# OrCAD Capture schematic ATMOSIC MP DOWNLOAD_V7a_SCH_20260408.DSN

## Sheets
1 1. TITLE: title: Atmosic MP Download Board - TITLE; rev: 7a
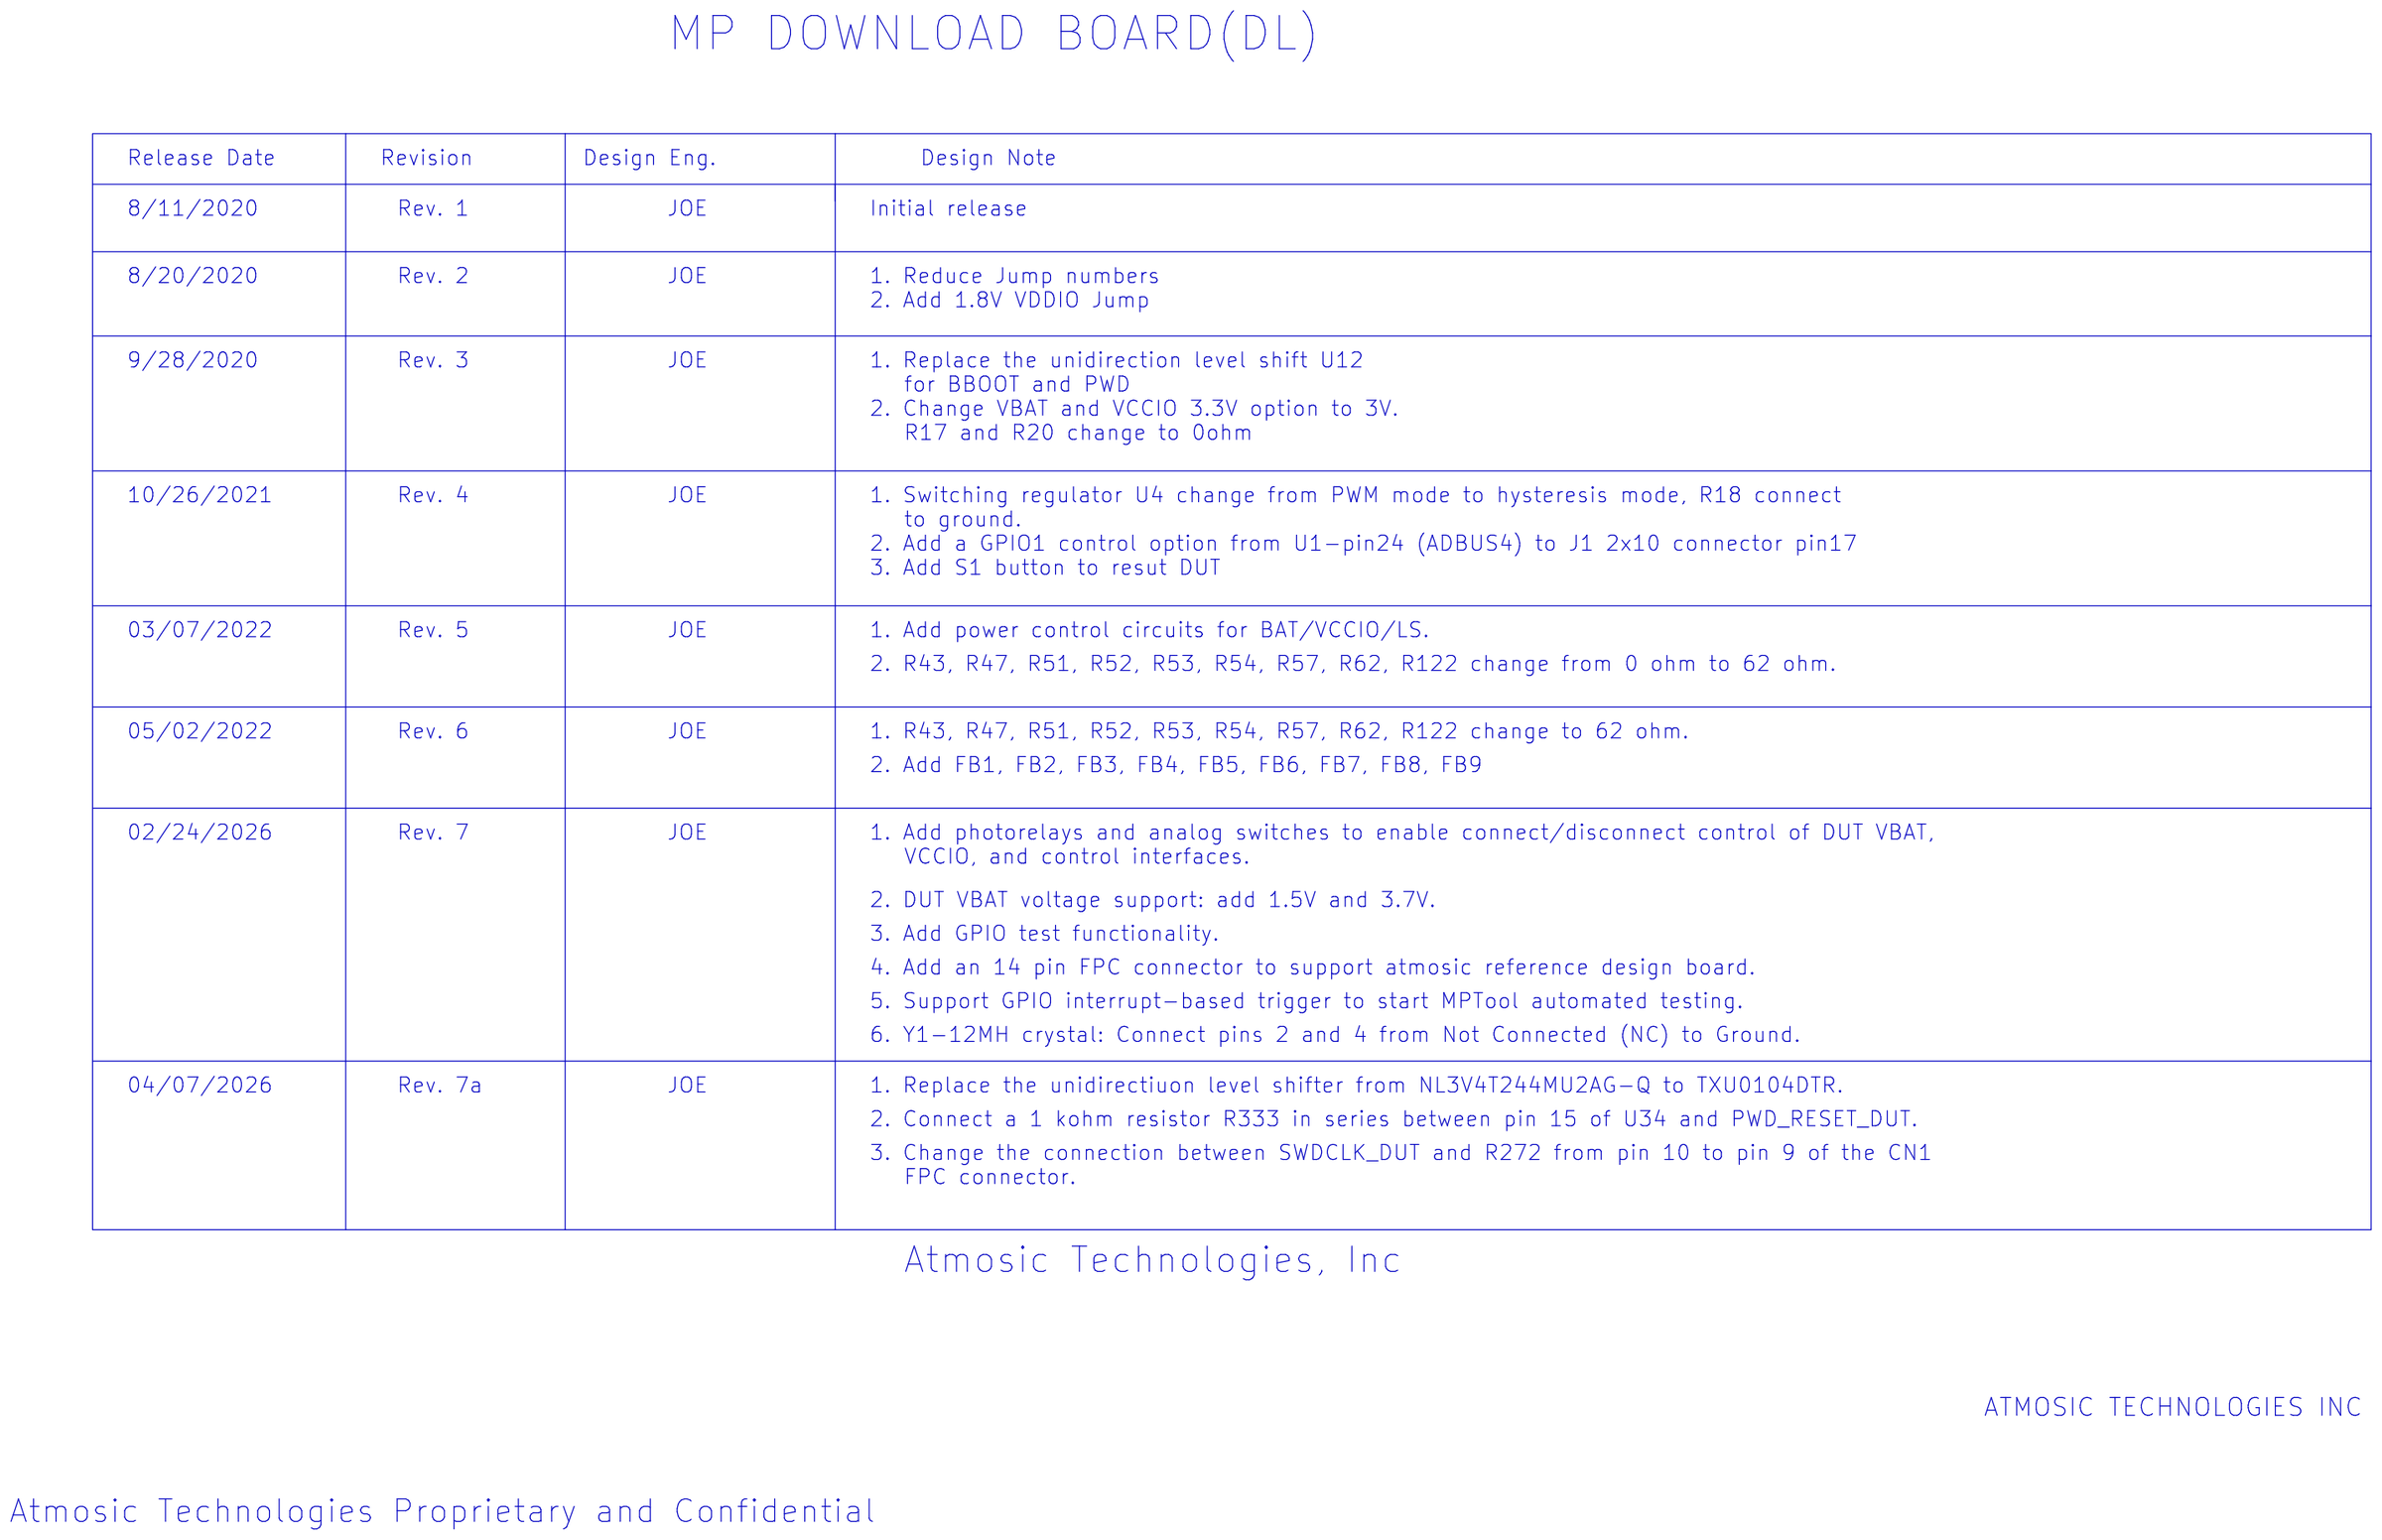
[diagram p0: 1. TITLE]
2 2. BLOCK_DIAGRAM: title: Atmosic MP Download Board - 2. BLOCK_DIAGRAM
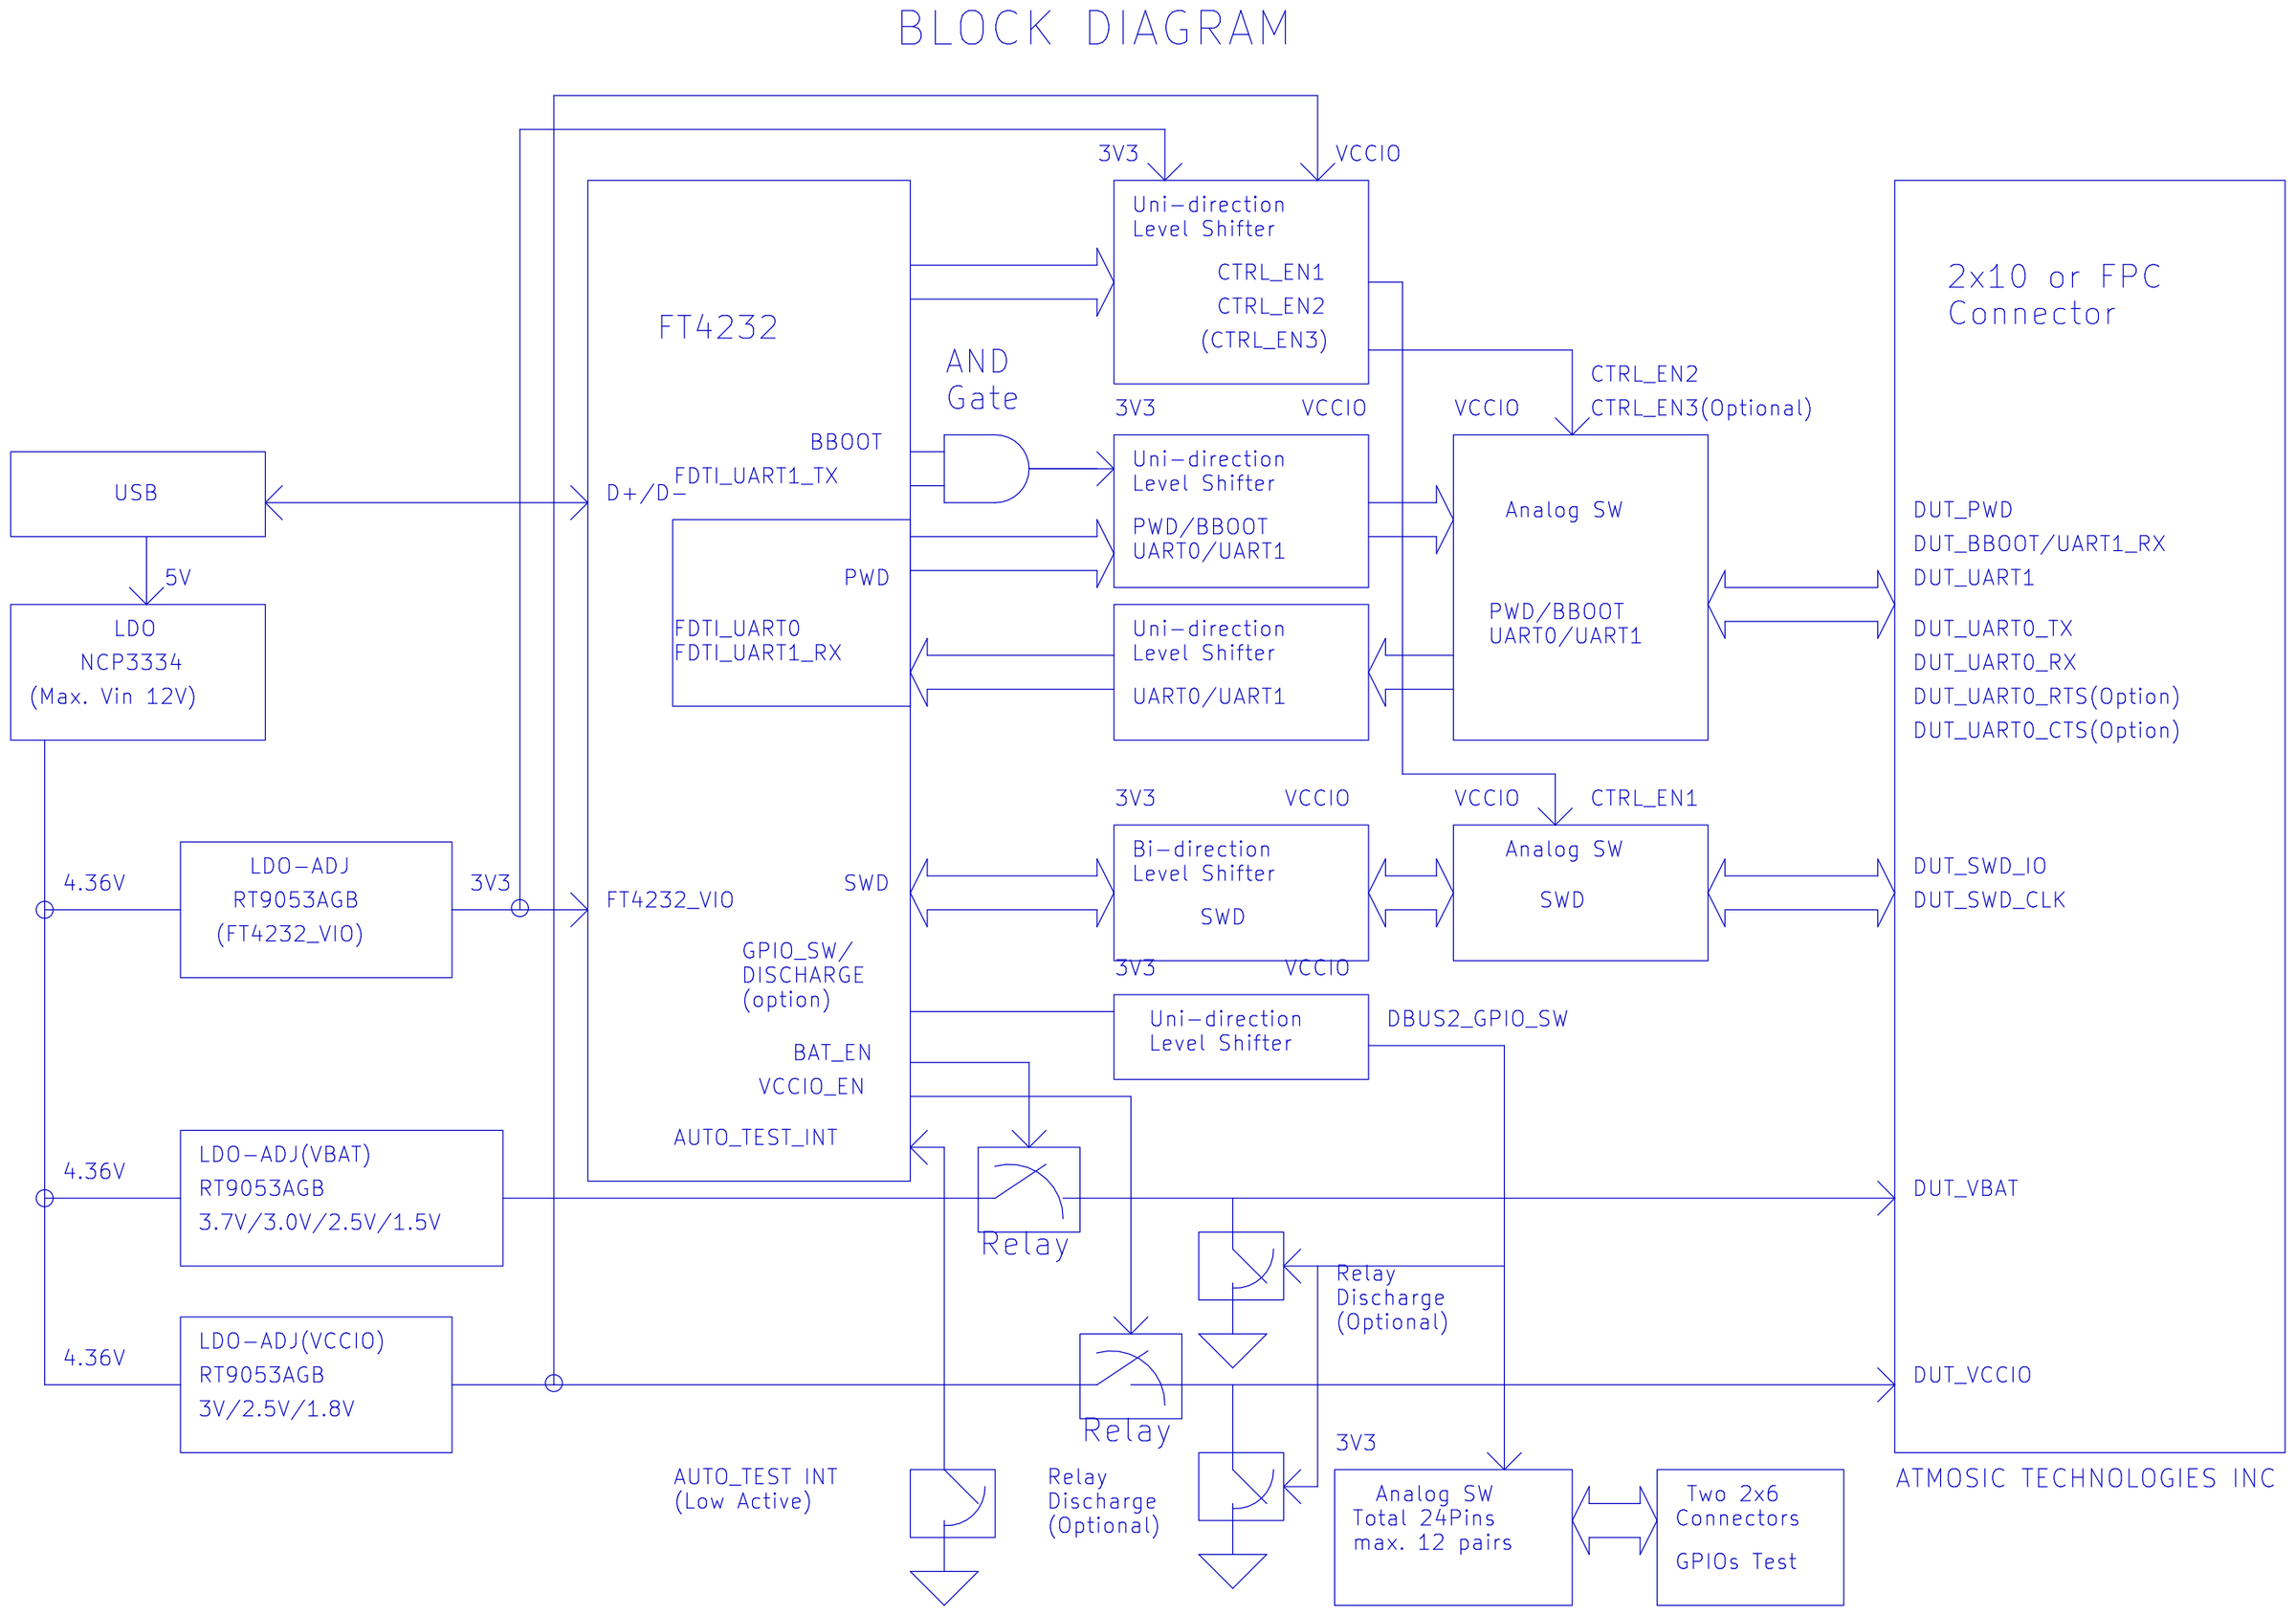
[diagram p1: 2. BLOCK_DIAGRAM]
3 3. POWER: size B; title: Atmosic MP Download Board - POWER
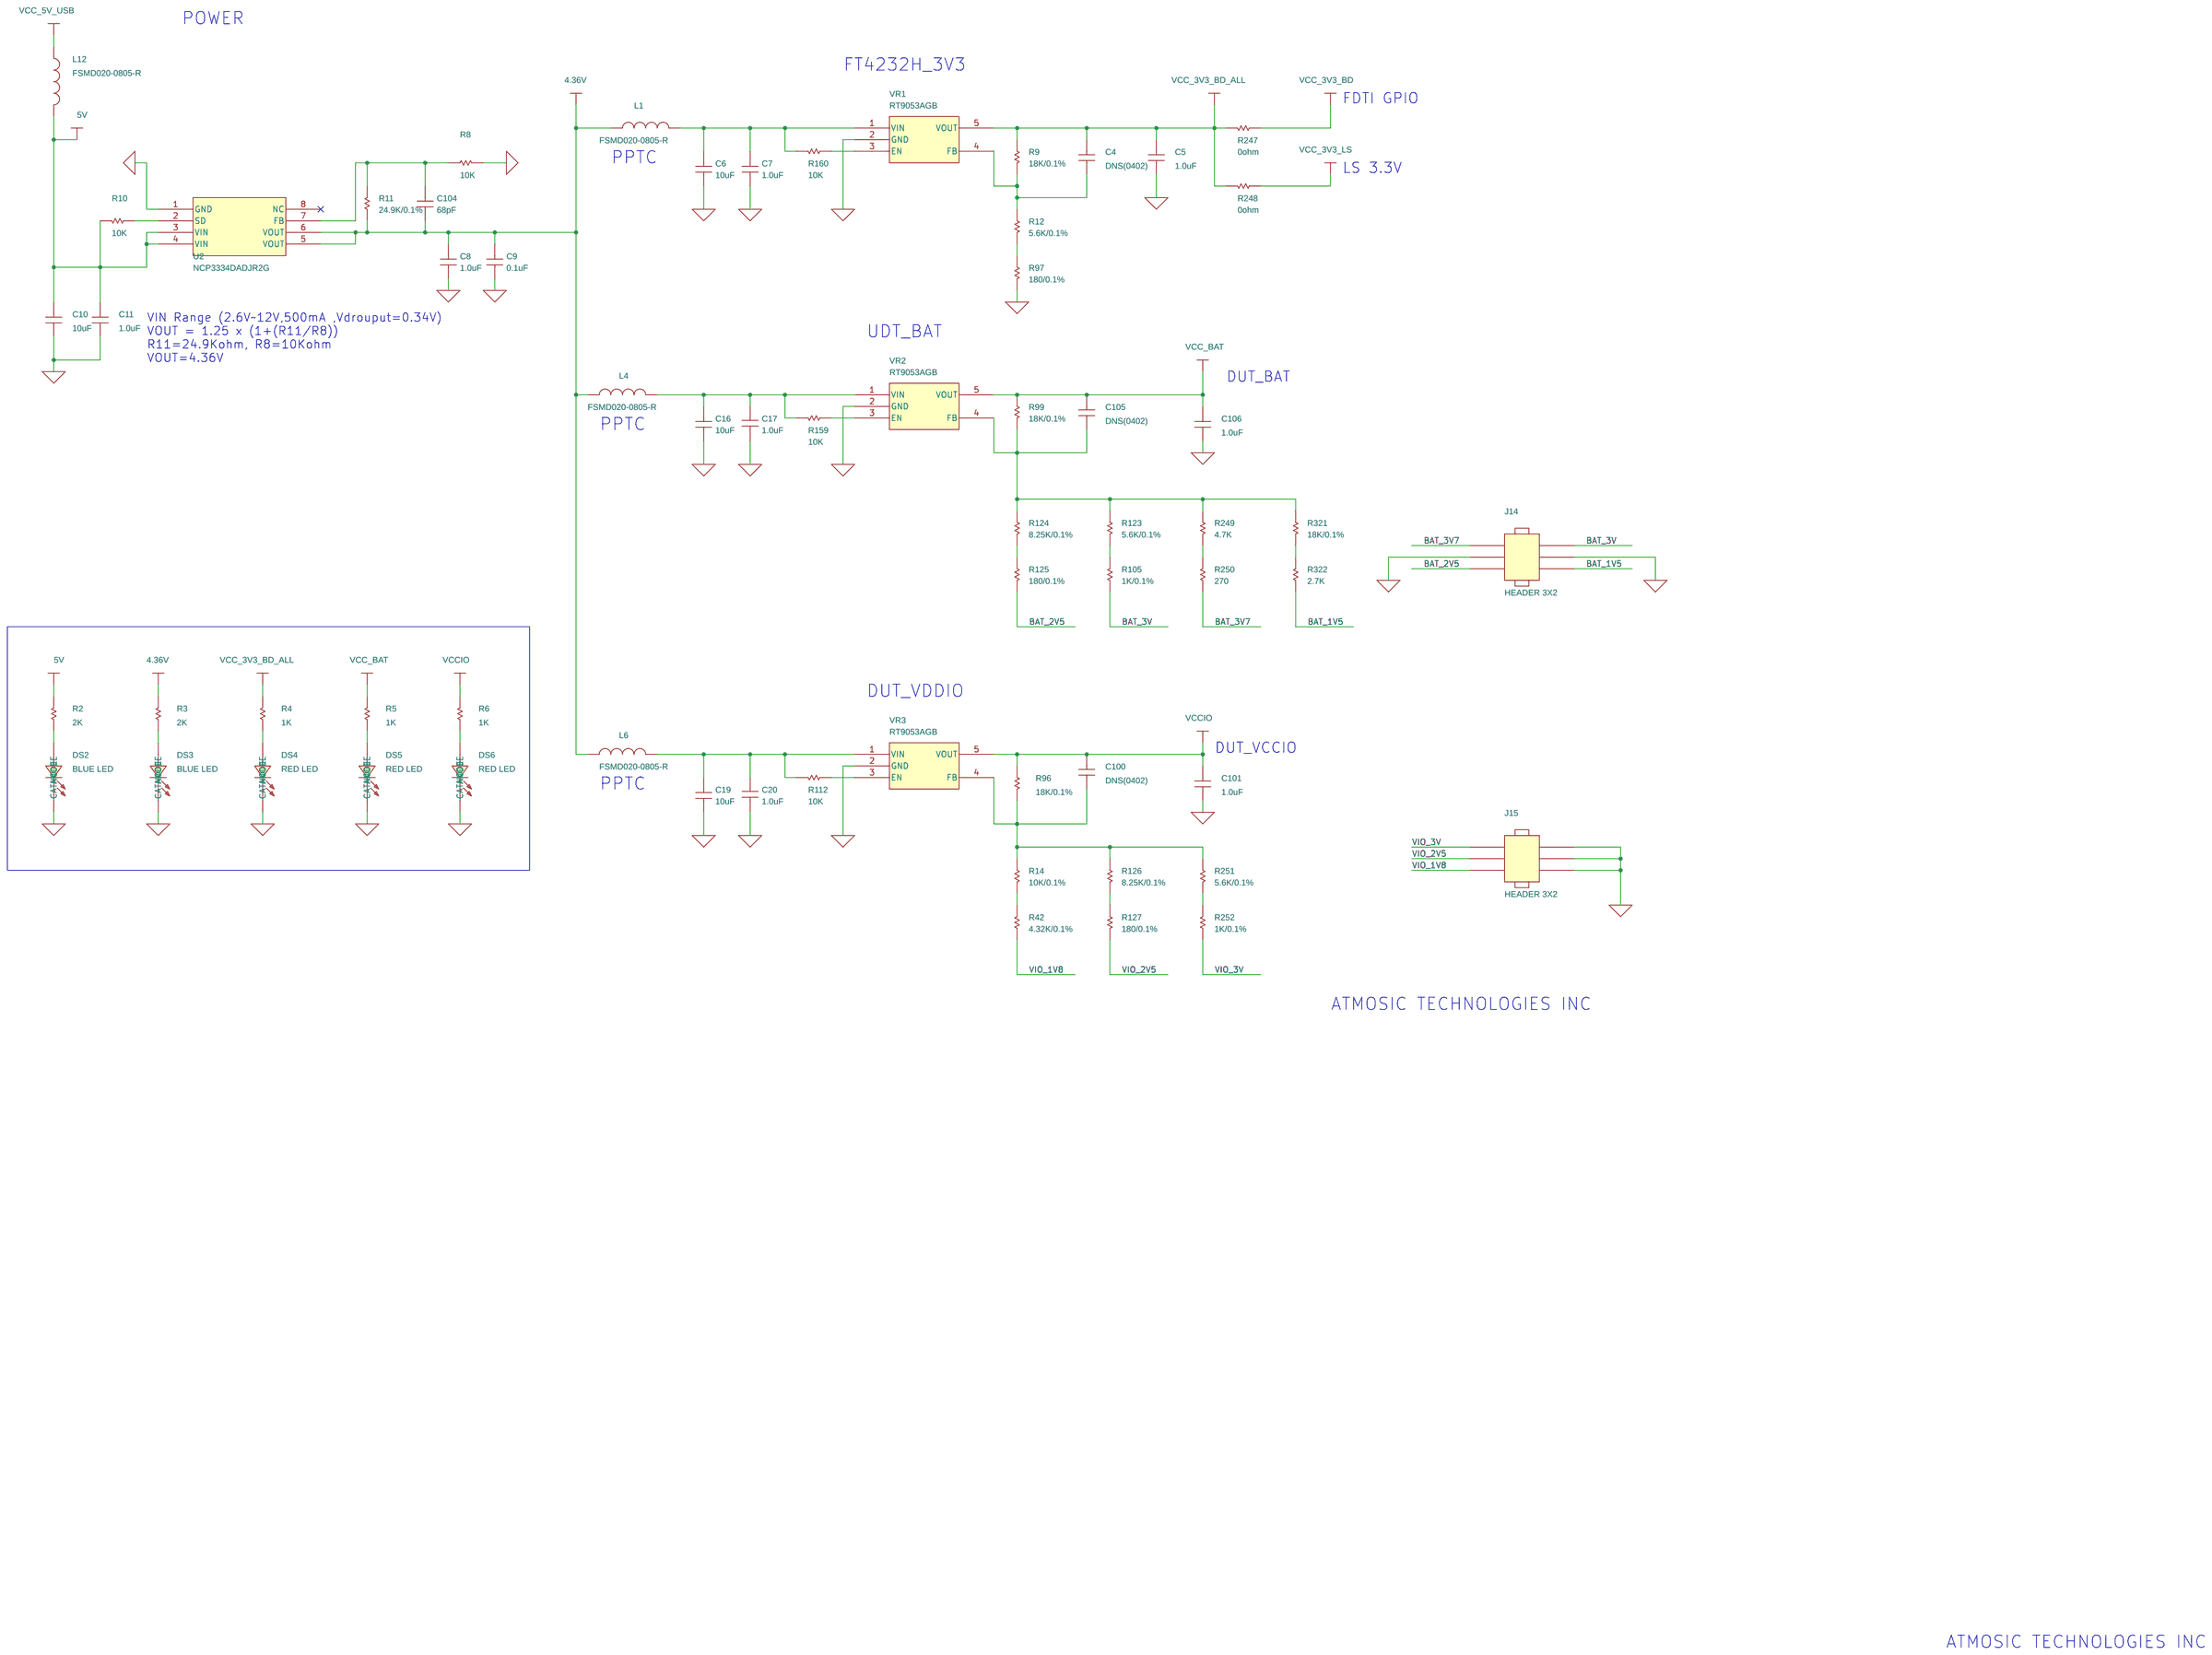
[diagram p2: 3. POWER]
4 4. FT4232H: size B; title: Atmosic MP Download Board -FT4232H
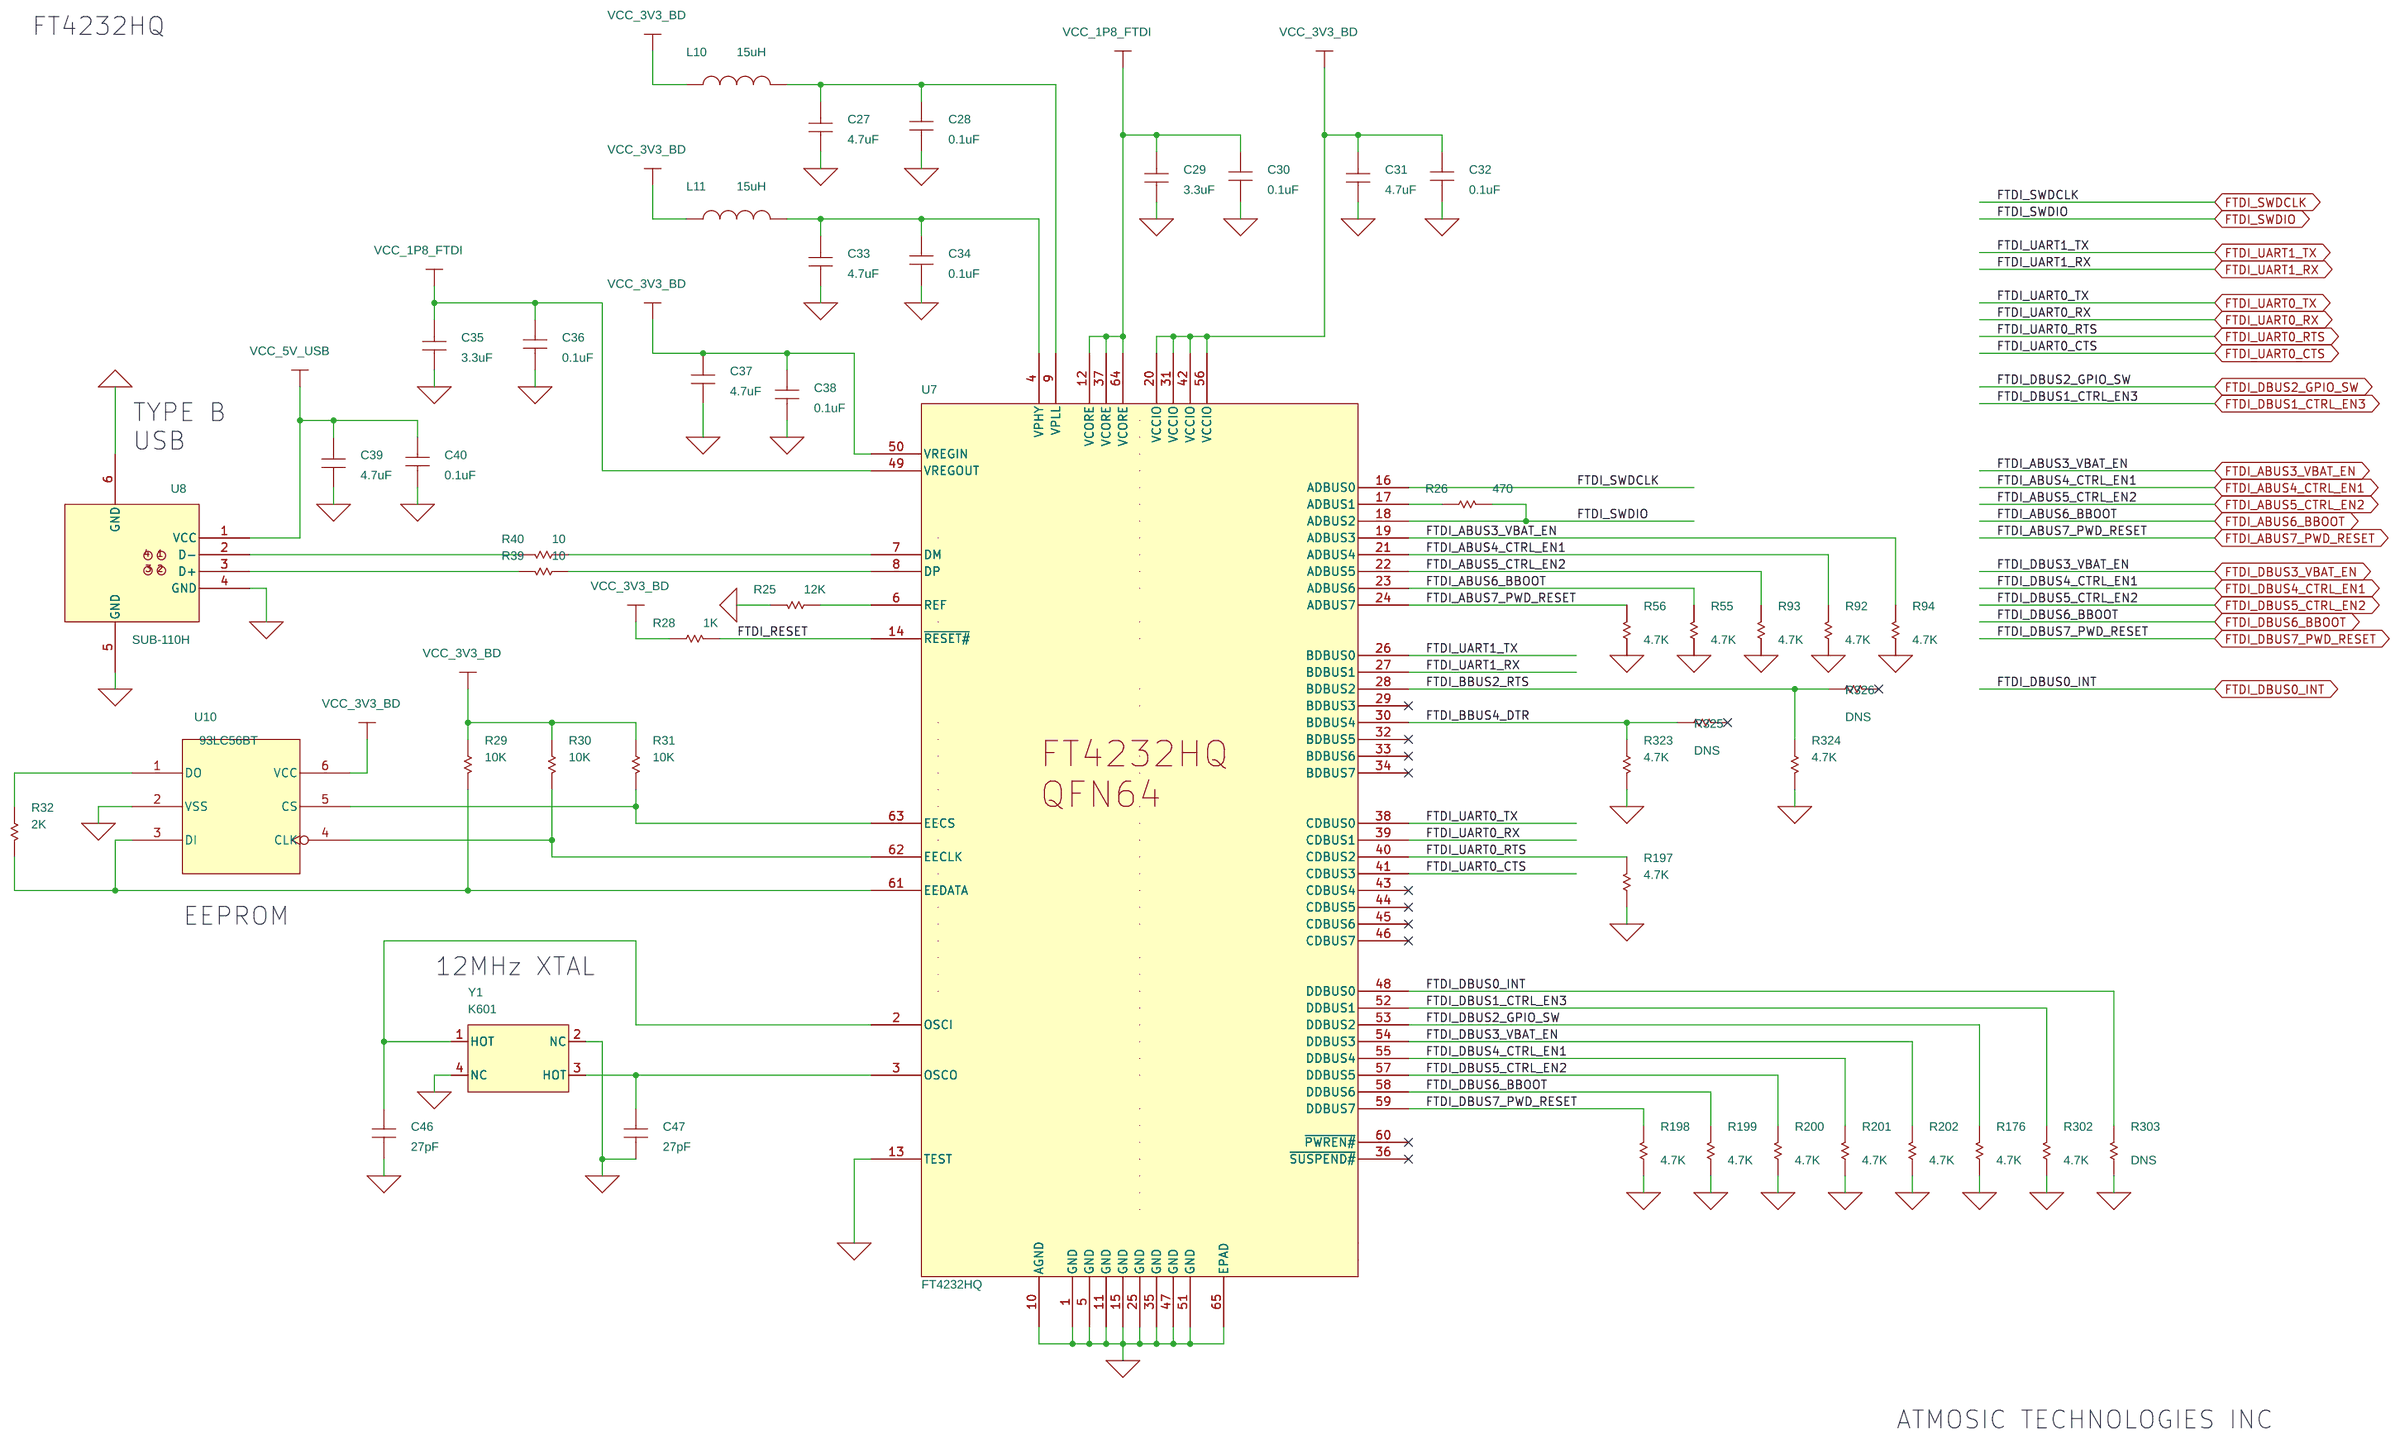
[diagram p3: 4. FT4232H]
5 5. FT4232H_2: size A; title: Atmosic MP Download Board FT4232H(2)
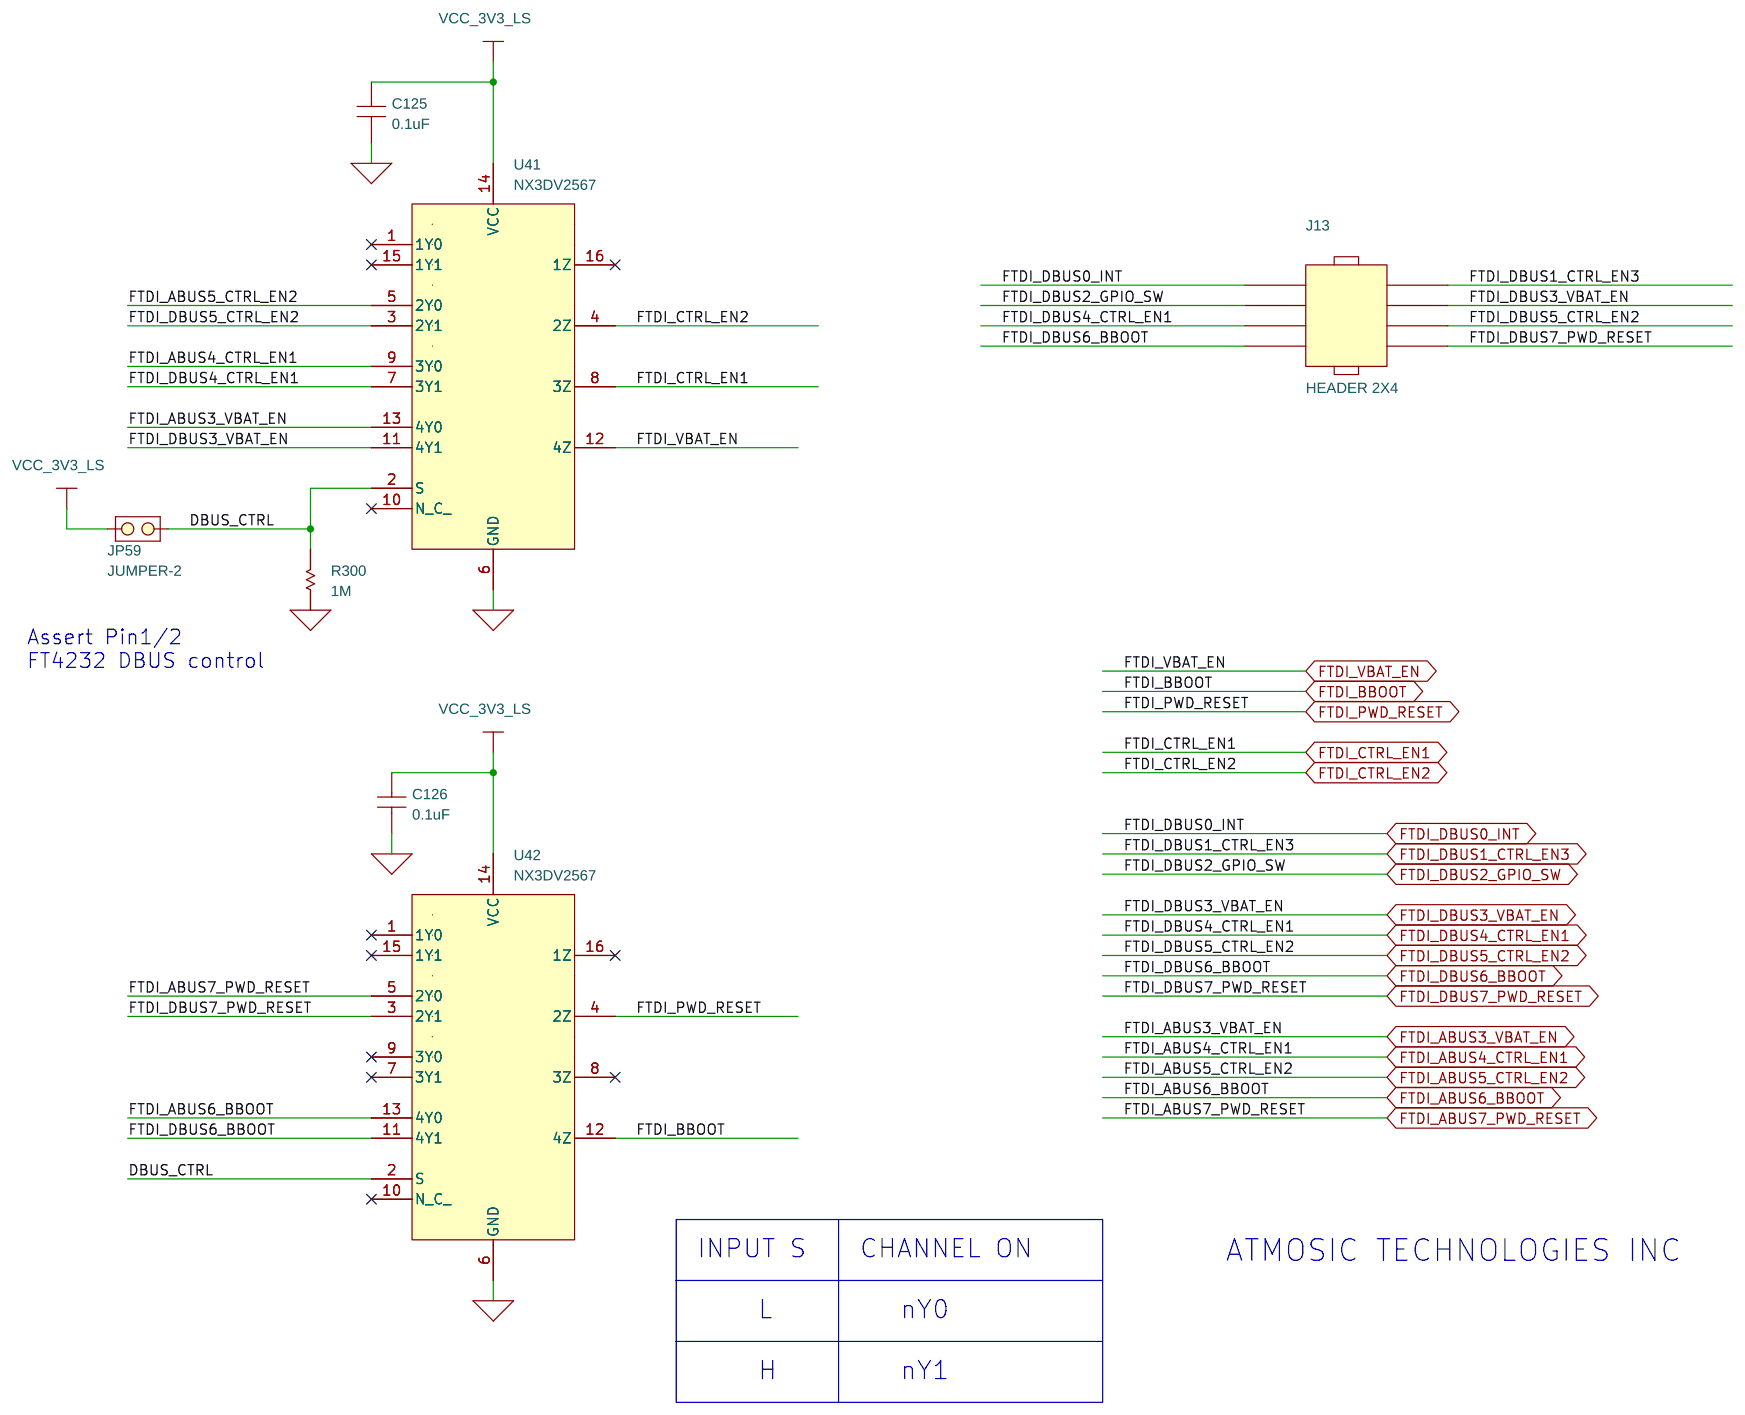
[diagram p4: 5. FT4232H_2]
6 6. LEVEL_SHIFTER: size B; title: Atmosic MP Download Board - LEVEL SHIFTER
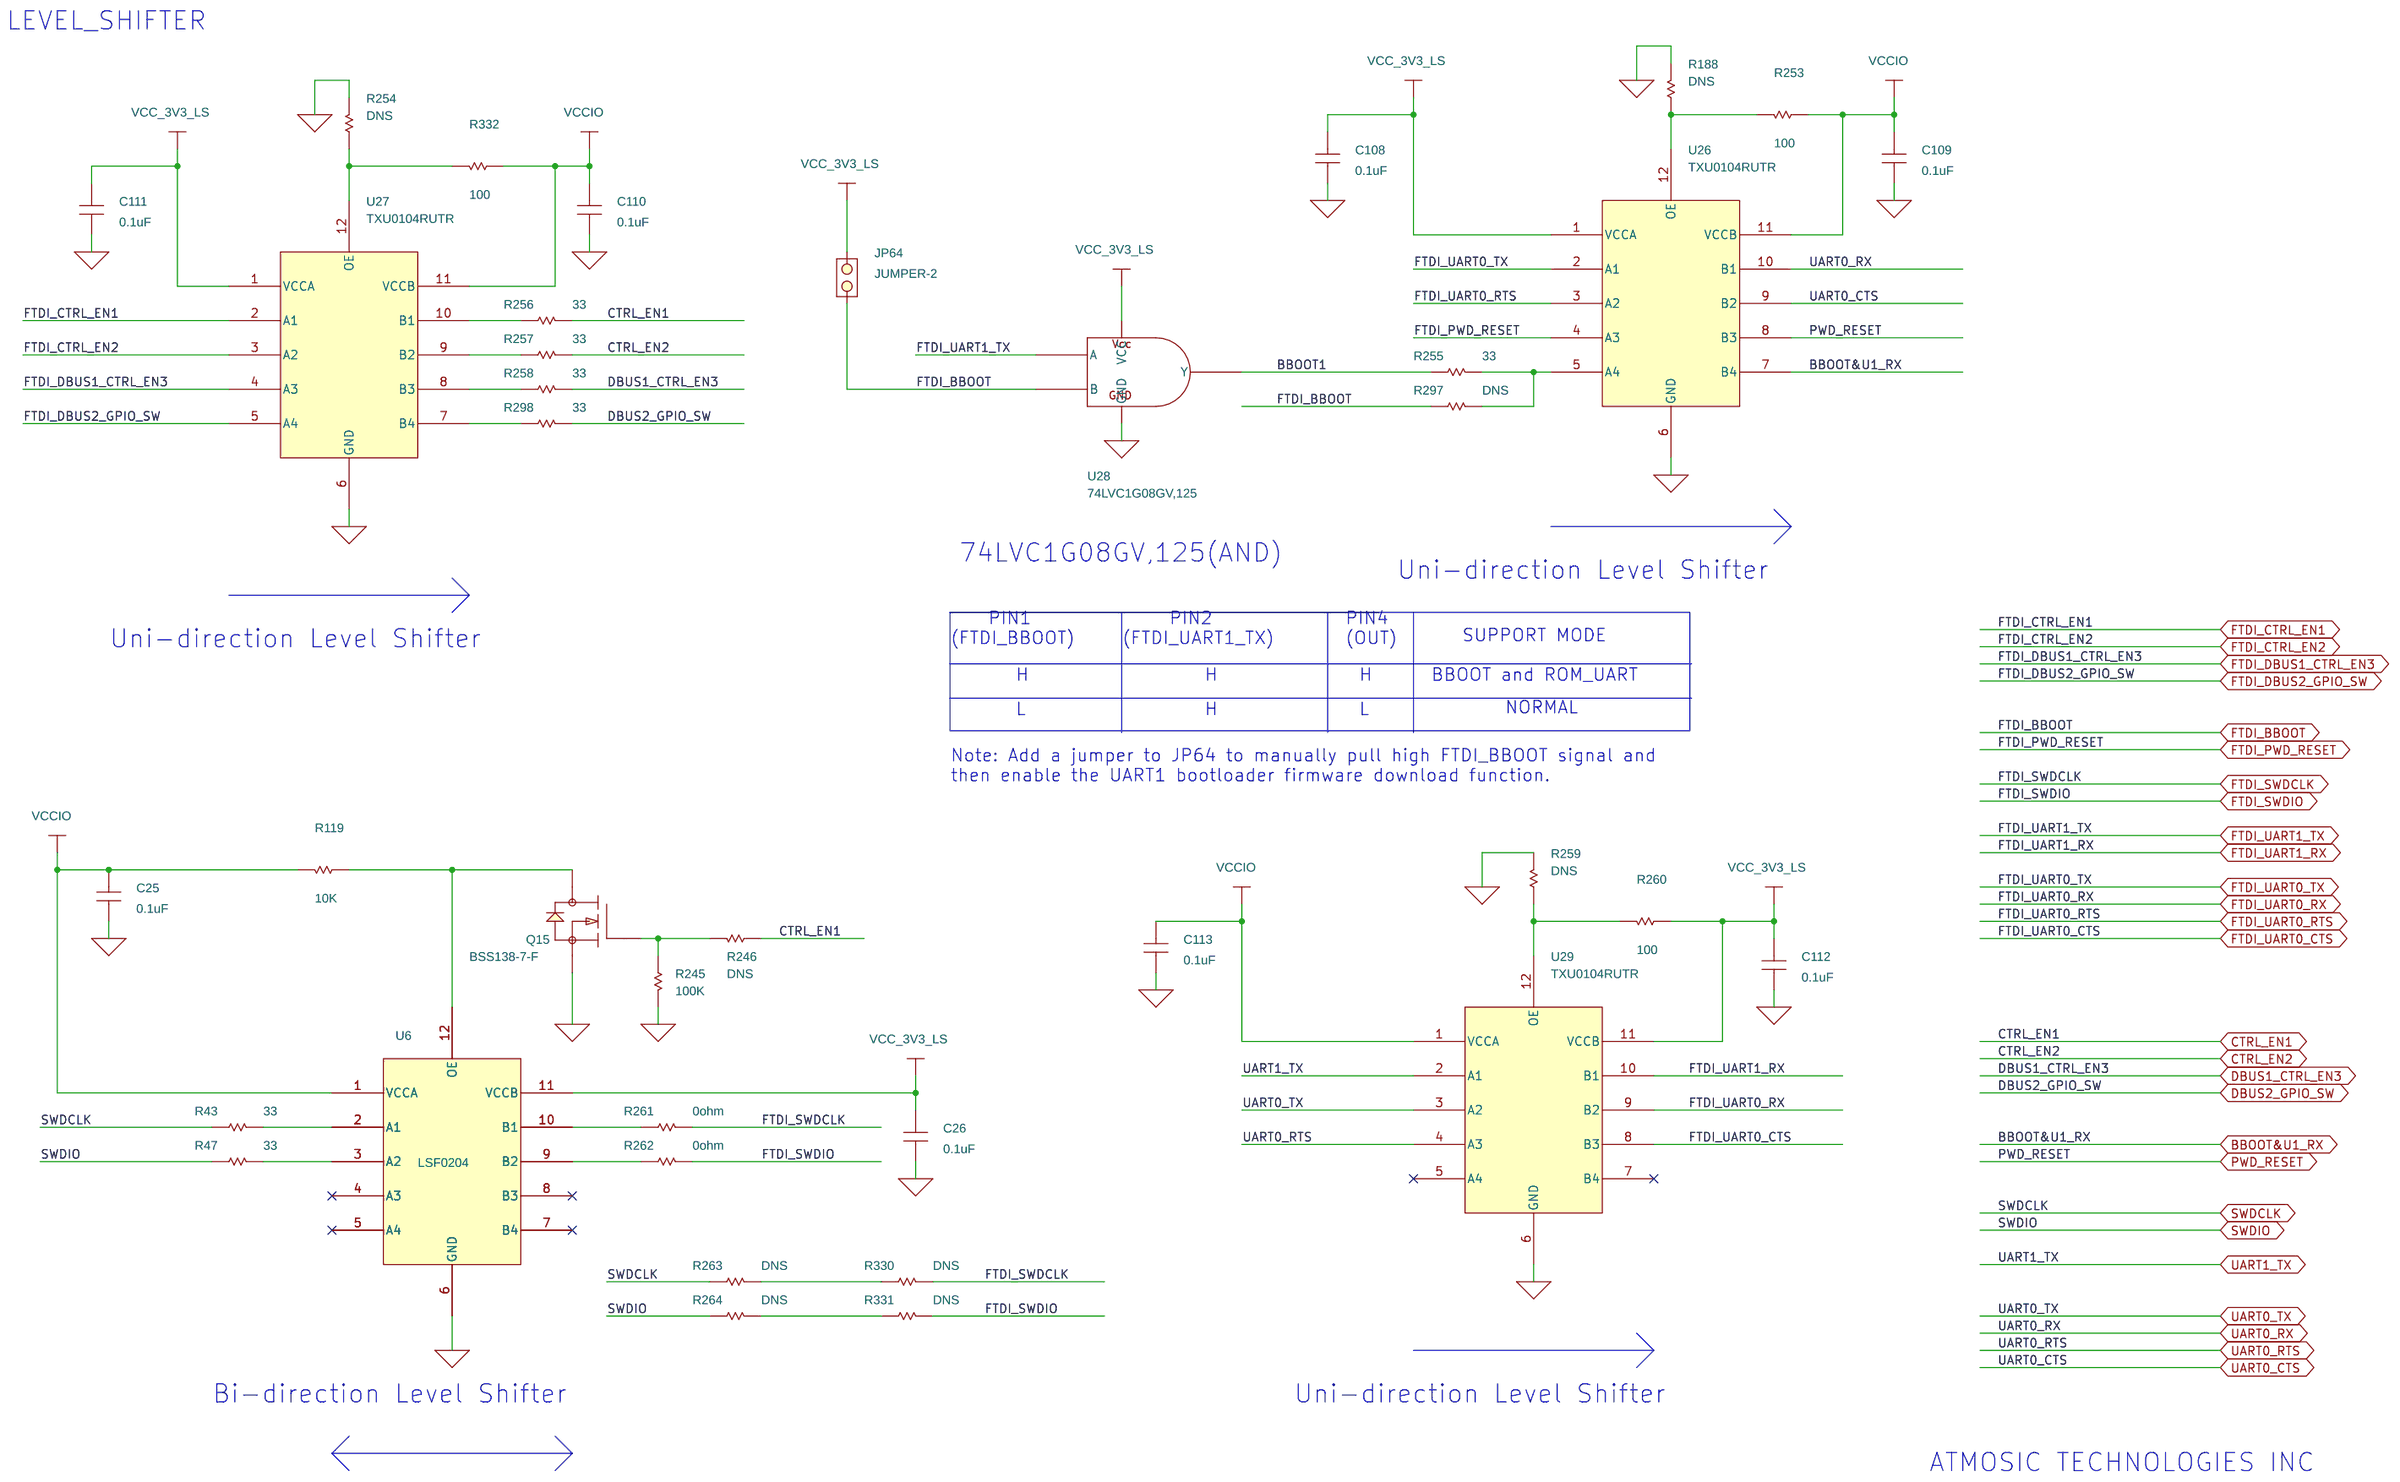
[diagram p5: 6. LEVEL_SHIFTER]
7 7. INTERFACE_ANALOG_SW: size B; title: Atmosic MP Download Board - INTERFACE and ANALOG SWITCH
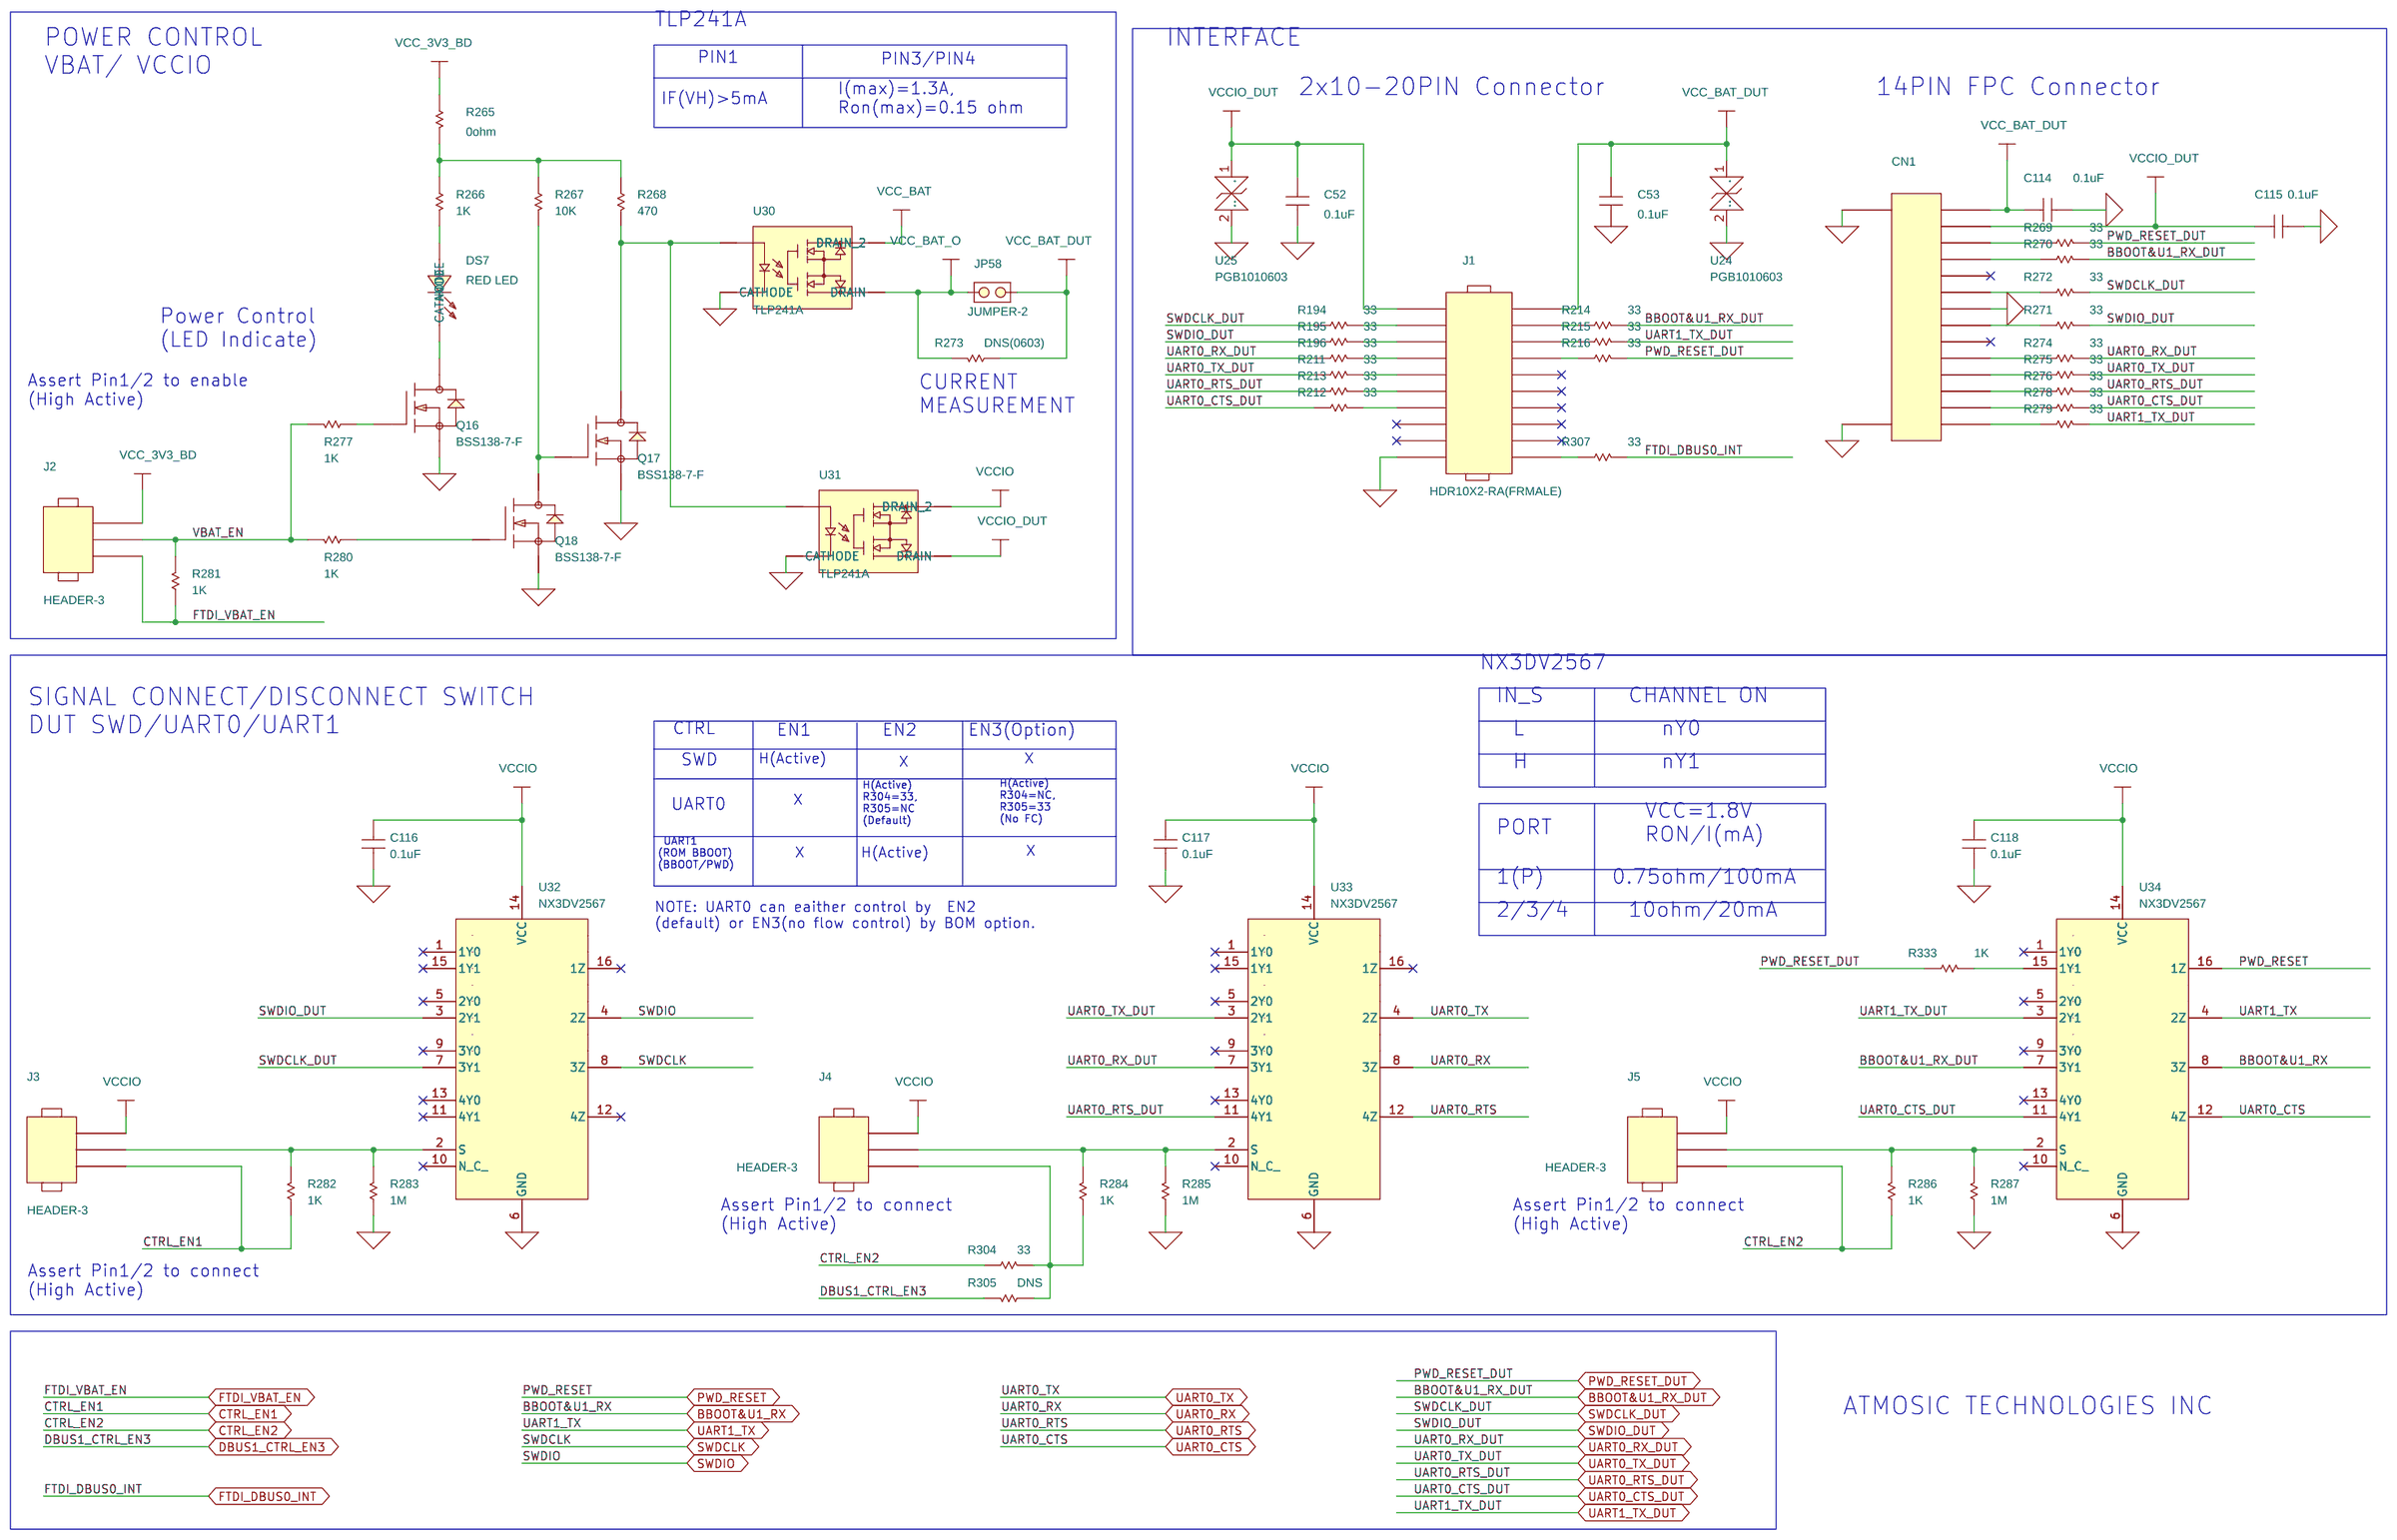
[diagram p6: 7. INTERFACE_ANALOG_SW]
8 8. GPIO TEST: size A; title: Atmosic MP Download Board - GPIO TEST
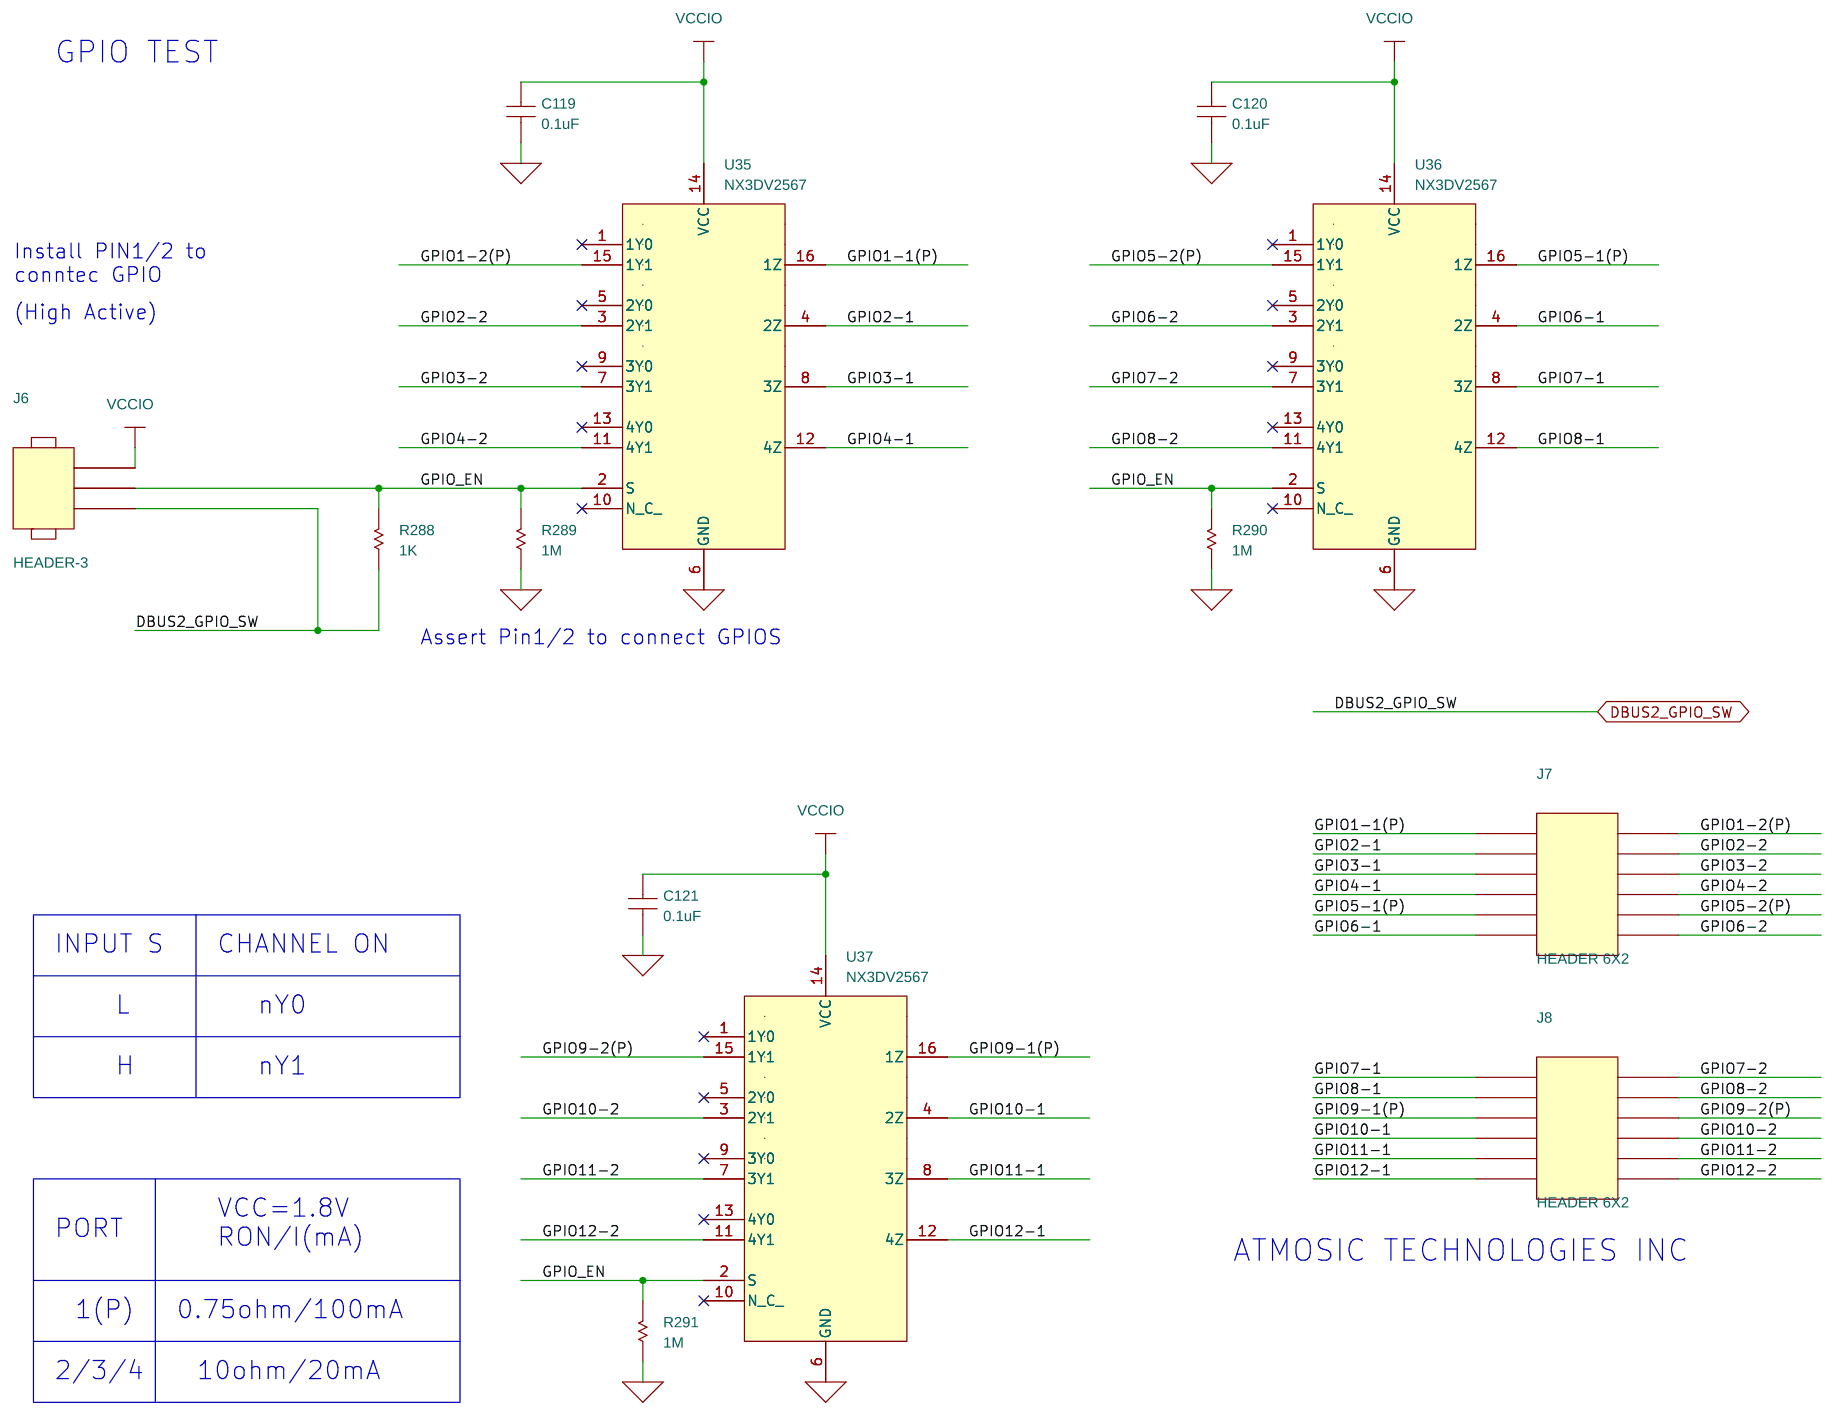
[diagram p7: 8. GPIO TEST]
9 A. DISCHARGE(OPTIONAL): size A; title: Atmosic MP Download Board - DISCHARGER(OPTIONAL)
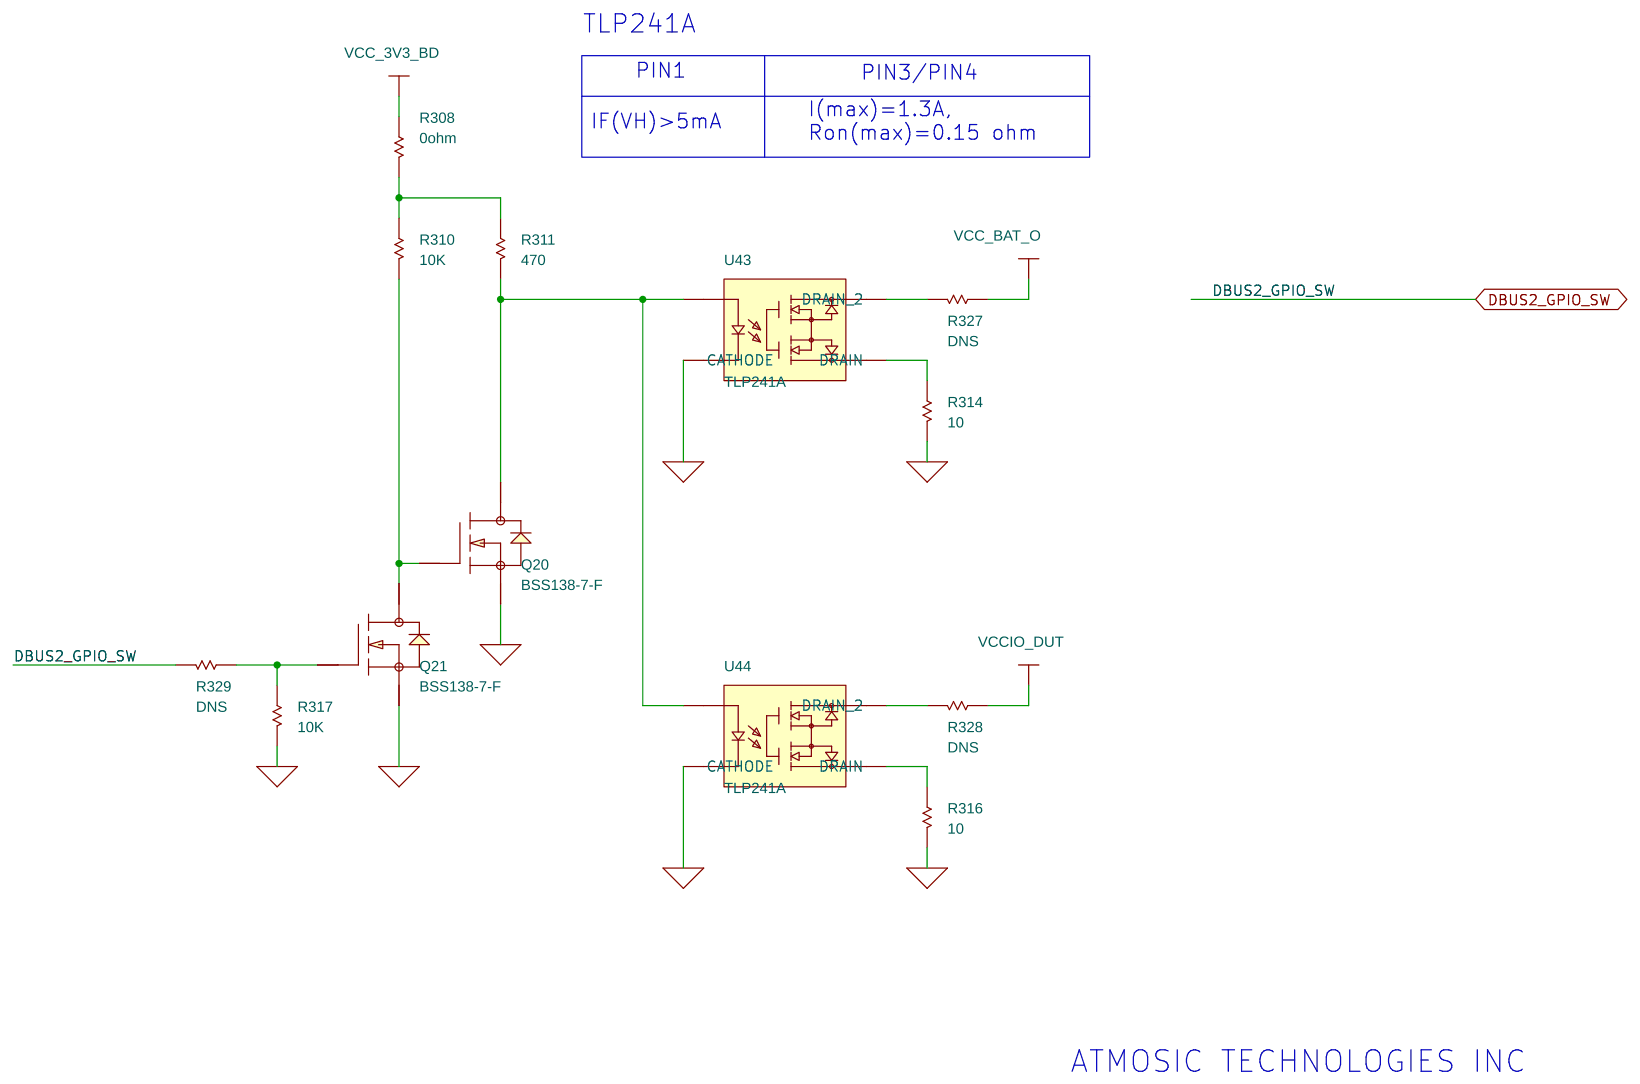
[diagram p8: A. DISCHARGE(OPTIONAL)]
10 9. RESET/AUTO_TEST/TEST PINS: size A; title: Atmosic MP Download Board - RESET/ AUTO TEST/ TEST PINS
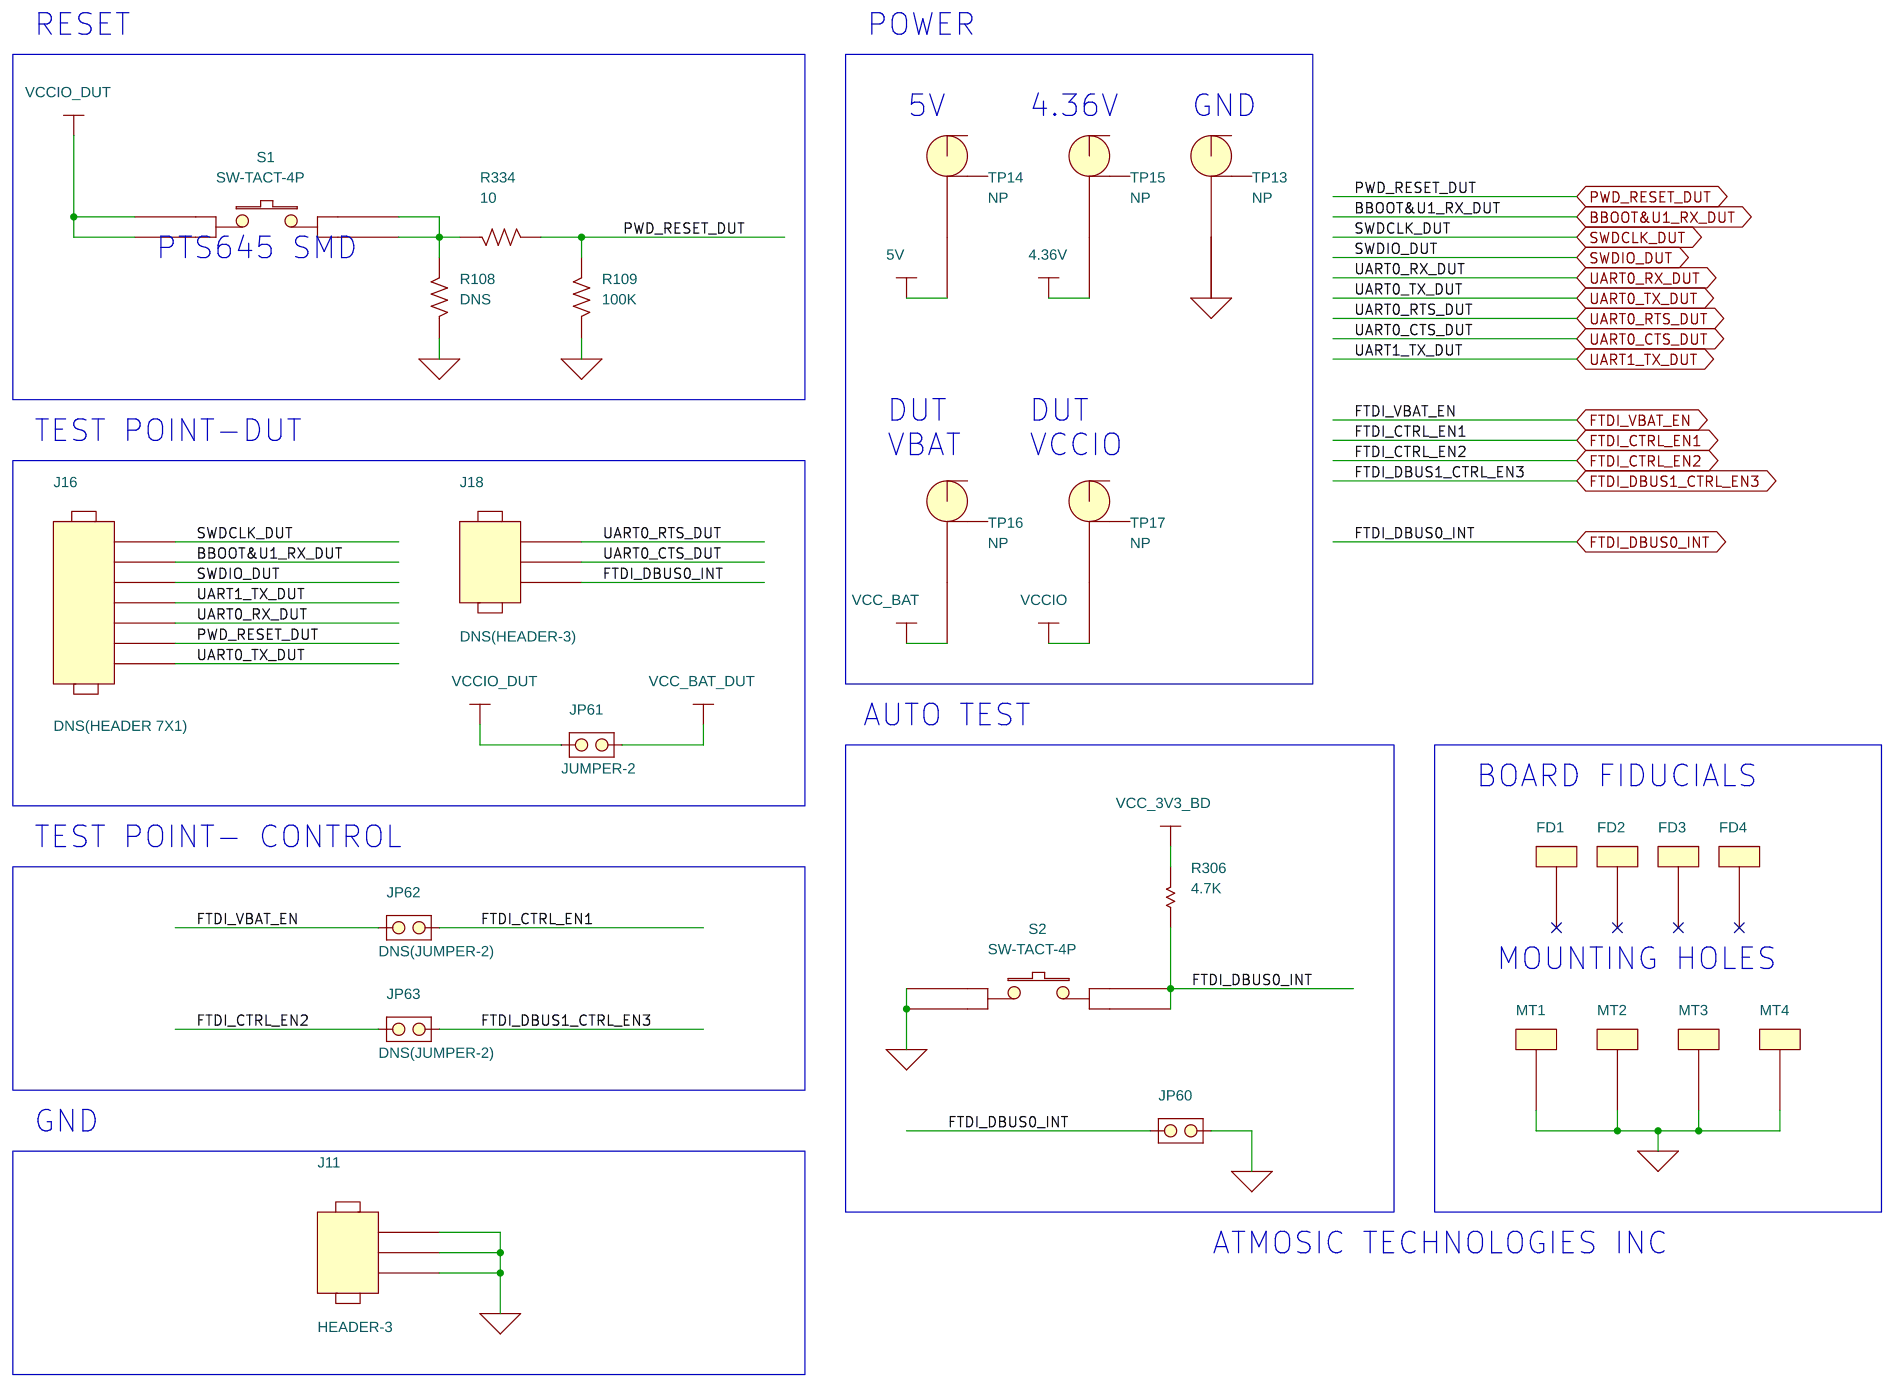
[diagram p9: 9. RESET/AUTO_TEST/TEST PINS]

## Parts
sheet 3. POWER
C4  DNS(0402)  [0402]
C5  1.0uF  [0402]
C6  10uF  [0402]
C7  1.0uF  [0402]
C8  1.0uF  [0402]
C9  0.1uF  [0402]
C10  10uF  [0402]
C11  1.0uF  [0402]
C16  10uF  [0402]
C17  1.0uF  [0402]
C19  10uF  [0402]
C20  1.0uF  [0402]
C100  DNS(0402)  [0402]
C101  1.0uF  [0402]
C104  68pF  [0402]
C105  DNS(0402)  [0402]
C106  1.0uF  [0402]
DS2  BLUE LED  [LED-0603]
DS3  BLUE LED  [LED-0603]
DS4  RED LED  [LED-0603]
DS5  RED LED  [LED-0603]
DS6  RED LED  [LED-0603]
J14  HEADER 3X2  [HDR3X2]
J15  HEADER 3X2  [HDR3X2]
L1  FSMD020-0805-R  [0805]
L4  FSMD020-0805-R  [0805]
L6  FSMD020-0805-R  [0805]
L12  FSMD020-0805-R  [0805]
R2  2K  [0402]
R3  2K  [0402]
R4  1K  [0402]
R5  1K  [0402]
R6  1K  [0402]
R8  10K  [0402]
R9  18K/0.1%  [0402]
R10  10K  [0402]
R11  24.9K/0.1%  [0402]
R12  5.6K/0.1%  [0402]
R14  10K/0.1%  [0402]
R42  4.32K/0.1%  [0402]
R96  18K/0.1%  [0402]
R97  180/0.1%  [0402]
R99  18K/0.1%  [0402]
R105  1K/0.1%  [0402]
R112  10K  [0402]
R123  5.6K/0.1%  [0402]
R124  8.25K/0.1%  [0402]
R125  180/0.1%  [0402]
R126  8.25K/0.1%  [0402]
R127  180/0.1%  [0402]
R159  10K  [0402]
R160  10K  [0402]
R247  0ohm  [0603]
R248  0ohm  [0603]
R249  4.7K  [0402]
R250  270  [0402]
R251  5.6K/0.1%  [0402]
R252  1K/0.1%  [0402]
R321  18K/0.1%  [0402]
R322  2.7K  [0402]
U2  NCP3334DADJR2G  [PSOP-8]
VR1  RT9053AGB  [SOT23-5]
VR2  RT9053AGB  [SOT23-5]
VR3  RT9053AGB  [SOT23-5]
sheet 4. FT4232H
C27  4.7uF  [0402]
C28  0.1uF  [0402]
C29  3.3uF  [0603]
C30  0.1uF  [0402]
C31  4.7uF  [0402]
C32  0.1uF  [0402]
C33  4.7uF  [0402]
C34  0.1uF  [0402]
C35  3.3uF  [0603]
C36  0.1uF  [0402]
C37  4.7uF  [0402]
C38  0.1uF  [0402]
C39  4.7uF  [0402]
C40  0.1uF  [0402]
C46  27pF  [0402]
C47  27pF  [0402]
L10  15uH  [0402]
L11  15uH  [0402]
R25  12K  [0402]
R26  470  [0402]
R28  1K  [0402]
R29  10K  [0402]
R30  10K  [0402]
R31  10K  [0402]
R32  2K  [0402]
R39  10  [0402]
R40  10  [0402]
R55  4.7K  [0402]
R56  4.7K  [0402]
R92  4.7K  [0402]
R93  4.7K  [0402]
R94  4.7K  [0402]
R176  4.7K  [0402]
R197  4.7K  [0402]
R198  4.7K  [0402]
R199  4.7K  [0402]
R200  4.7K  [0402]
R201  4.7K  [0402]
R202  4.7K  [0402]
R302  4.7K  [0402]
R303  DNS  [0402]
R323  4.7K  [0402]
R324  4.7K  [0402]
R325  DNS  [0402]
R326  DNS  [0402]
U7  FT4232HQ  [QFN-64-9X9MM-0.5]
U8  SUB-110H  [SUB-110H]
U10  93LC56BT  [SOT23-6]
Y1  K601  [CRY-SMD4-3.2X2.5MM]
sheet 5. FT4232H_2
C125  0.1uF  [0402]
C126  0.1uF  [0402]
J13  HEADER 2X4  [HDR4X2]
JP59  JUMPER-2  [HDR1X2]
R300  1M  [0402]
U41  NX3DV2567  [XQFN16]
U42  NX3DV2567  [XQFN16]
sheet 6. LEVEL_SHIFTER
C25  0.1uF  [0402]
C26  0.1uF  [0402]
C108  0.1uF  [0402]
C109  0.1uF  [0402]
C110  0.1uF  [0402]
C111  0.1uF  [0402]
C112  0.1uF  [0402]
C113  0.1uF  [0402]
JP64  JUMPER-2  [HDR1X2]
Q15  BSS138-7-F  [SOT23]
R43  33  [0402]
R47  33  [0402]
R119  10K  [0402]
R188  DNS  [0402]
R245  100K  [0402]
R246  DNS  [0402]
R253  100  [0402]
R254  DNS  [0402]
R255  33  [0402]
R256  33  [0402]
R257  33  [0402]
R258  33  [0402]
R259  DNS  [0402]
R260  100  [0402]
R261  0ohm  [0402]
R262  0ohm  [0402]
R263  DNS  [0402]
R264  DNS  [0402]
R297  DNS  [0402]
R298  33  [0402]
R330  DNS  [0402]
R331  DNS  [0402]
R332  100  [0402]
U6  LSF0204  [QFN-12-1.7X2]
U26  TXU0104RUTR  [QFN-12-1.7X2]
U27  TXU0104RUTR  [QFN-12-1.7X2]
U28  74LVC1G08GV,125  [SOT23-5]
U29  TXU0104RUTR  [QFN-12-1.7X2]
sheet 7. INTERFACE_ANALOG_SW
C52  0.1uF  [0402]
C53  0.1uF  [0402]
C114  0.1uF  [0402]
C115  0.1uF  [0402]
C116  0.1uF  [0402]
C117  0.1uF  [0402]
C118  0.1uF  [0402]
CN1  05002HR-14CE  [FFC/0.5mm/14PIN]
DS7  RED LED  [LED-0603]
J1  HDR10X2-RA(FRMALE)  [HDR10X2-RT-MATE]
J2  HEADER-3  [HDR1X3]
J3  HEADER-3  [HDR1X3]
J4  HEADER-3  [HDR1X3]
J5  HEADER-3  [HDR1X3]
JP58  JUMPER-2  [HDR1X2]
Q16  BSS138-7-F  [SOT23]
Q17  BSS138-7-F  [SOT23]
Q18  BSS138-7-F  [SOT23]
R194  33  [0402]
R195  33  [0402]
R196  33  [0402]
R211  33  [0402]
R212  33  [0402]
R213  33  [0402]
R214  33  [0402]
R215  33  [0402]
R216  33  [0402]
R265  0ohm  [0603]
R266  1K  [0402]
R267  10K  [0402]
R268  470  [0402]
R269  33  [0402]
R270  33  [0402]
R271  33  [0402]
R272  33  [0402]
R273  DNS(0603)  [0603]
R274  33  [0402]
R275  33  [0402]
R276  33  [0402]
R277  1K  [0402]
R278  33  [0402]
R279  33  [0402]
R280  1K  [0402]
R281  1K  [0402]
R282  1K  [0402]
R283  1M  [0402]
R284  1K  [0402]
R285  1M  [0402]
R286  1K  [0402]
R287  1M  [0402]
R304  33  [0402]
R305  DNS  [0402]
R307  33  [0402]
R333  1K  [0402]
U24  PGB1010603  [0603]
U25  PGB1010603  [0603]
U30  TLP241A  [DIP4_TOS]
U31  TLP241A  [DIP4_TOS]
U32  NX3DV2567  [XQFN16]
U33  NX3DV2567  [XQFN16]
U34  NX3DV2567  [XQFN16]
sheet 8. GPIO TEST
C119  0.1uF  [0402]
C120  0.1uF  [0402]
C121  0.1uF  [0402]
J6  HEADER-3  [HDR1X3]
J7  HEADER 6X2  [HDR6X2-SP]
J8  HEADER 6X2  [HDR6X2-SP]
R288  1K  [0402]
R289  1M  [0402]
R290  1M  [0402]
R291  1M  [0402]
U35  NX3DV2567  [XQFN16]
U36  NX3DV2567  [XQFN16]
U37  NX3DV2567  [XQFN16]
sheet 9. RESET/AUTO_TEST/TEST PINS
FD1  TEST POINT  [FID-G]
FD2  TEST POINT  [FID-G]
FD3  TEST POINT  [FID-G]
FD4  TEST POINT  [FID-G]
J11  HEADER-3  [HDR1X3]
J16  DNS(HEADER 7X1)  [HDR1X7]
J18  DNS(HEADER-3)  [HDR1X3]
JP60  JUMPER-2  [HDR1X2]
JP61  JUMPER-2  [HDR1X2]
JP62  DNS(JUMPER-2)  [HDR1X2]
JP63  DNS(JUMPER-2)  [HDR1X2]
MT1  TEST POINT  [HOLE-250R125]
MT2  TEST POINT  [HOLE-250R125]
MT3  TEST POINT  [HOLE-250R125]
MT4  TEST POINT  [HOLE-250R125]
R108  DNS  [0402]
R109  100K  [0402]
R306  4.7K  [0402]
R334  10  [0402]
S1  SW-TACT-4P  [SWI-SM-PTS645]
S2  SW-TACT-4P  [SWI-SM-PTS645]
TP13  NP  [TEST1]
TP14  NP  [TEST1]
TP15  NP  [TEST1]
TP16  NP  [TEST1]
TP17  NP  [TEST1]
sheet A. DISCHARGE(OPTIONAL)
Q20  BSS138-7-F  [SOT23]
Q21  BSS138-7-F  [SOT23]
R308  0ohm  [0603]
R310  10K  [0402]
R311  470  [0402]
R314  10  [0402]
R316  10  [0402]
R317  10K  [0402]
R327  DNS  [0402]
R328  DNS  [0402]
R329  DNS  [0402]
U43  TLP241A  [DIP4_TOS]
U44  TLP241A  [DIP4_TOS]

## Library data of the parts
C4 C100 C105 = SMALL_CAP: Part Number: 01-2000016
C5 C7 C8 C11 C17 C20 C101 C106 = SMALL_CAP: MF: Murata Electronics; Manufacture_Name: MURATA; Manufacture_Part_Number: GRM155R61E105MA12D; Part Number: 01-2000037; Price: 0.003; Datasheet: https://www.digikey.com/en/products/detail/murata-electronics/GRM155R61E105MA12D/4905141
C6 C10 C16 C19 = SMALL_CAP: MF: Murata Electronics; Manufacture_Name: MURATA; Manufacture_Part_Number: GRM155R60J106ME15D; Part Number: 01-2000011; Price: 0.00378; Datasheet: https://www.digikey.com/product-detail/en/murata-electronics-north-america/GRM155R60J106ME15D/490-13238-1-ND/5877446
C9 C25 C26 C28 C30 C32 C34 C36 C38 C40 C52 C53 = SMALL_CAP: MF: Murata Electronics; Manufacture_Name: MURATA; Manufacture_Part_Number: GRM155R61E104KA87; Part Number: 01-2000043; Price: 0.0013; Datasheet: https://www.murata.com/products/productdetail.aspx?partno=GRM155R61E104KA87%23
C104 = SMALL_CAP: MF: WALSIN; Manufacture_Name: WALSIN; Manufacture_Part_Number: 0402N680J500CT; Part Number: 01-2000033; Price: 0.001
DS2 DS3 = LED: MF: Lite-On Inc.; Manufacture_Name: Lite-On Inc.; Manufacture_Part_Number: LTST-C191TBKT; Part Number: 06-0000028; Price: 0.008
DS4-DS7 = LED: MF: Lite-On Inc.; Manufacture_Name: Lite-On Inc.; Manufacture_Part_Number: LTST-C191KRKT; Part Number: 06-0000029; Price: 0.008
J14 J15 = HEADER_3X2: Manufacture_Name: Amphenol ICC (FCI); Manufacture_Part_Number: 68602-206HLF; Part Number: 08-0000026
L1 L4 L6 L12 = INDUCTOR: MF: Fuxetec; Manufacture_Name: FUXETEC; Part Description: RESETTABLE FUSE - SMD, 0805 SIZE; Part Number: 02-4000003; Price: 0.08
R2 R3 R32 = SMALL_R1: MF: WALSIN; Manufacture_Name: WALSIN; Manufacture_Part_Number: WR04X2001FTL; Part Number: 03-2000034; Price: 0.0002
R4-R6 R28 R266 R333 = SMALL_R1: MF: WALSIN; Manufacture_Name: WALSIN; Manufacture_Part_Number: WR04X1001FTL; Part Description: RES 1K OHM 1% 0402; Part Number: 03-2000028; Price: 0.0002; Datasheet: https://www.digikey.com/en/products/detail/walsin-technology-corporation/WR04X1001FTL/13240628?s=N4IgTCBcDaIOoCUAMAWAGgRiUjAxAKgDIgC6AvkA
R8 R10 R29-R31 R119 = SMALL_R1: MF: WALSIN; Manufacture_Name: WALSIN; Manufacture_Part_Number: WR04X1002FTL; Part Description: RES 10K OHM 1% 1/16W 0402; Part Number: 03-2000022; Price: 0.0002; Datasheet: https://www.digikey.com/en/products/detail/walsin-technology-corporation/WR04X1002FTL/13241339?s=N4IgTCBcDaIOoCUAMAWAGgRiUsAxAKgDIgC6AvkA
R9 R96 R99 = SMALL_R1: MF: YAGEO; Manufacture_Name: YAGEO; Manufacture_Part_Number: RT0402BRE0718KL; Part Description: RES 18K OHM 0.1% 0402; Part Number: 03-2000083
R11 = SMALL_R1: MF: Panasonic Electronic; Manufacture_Name: PANASONIC; Manufacture_Part_Number: ERA-2AEB2492X; Part Description: RES 24.9K OHM 0.1% 0402; Part Number: 03-2000084
R12 R123 R251 = SMALL_R1: MF: Panasonic Electronic; Manufacture_Name: PANASONIC; Manufacture_Part_Number: ERA-2AEB562X; Part Description: RES 5.6K OHM 0.1% 0402; Part Number: 03-2000085
R14 = SMALL_R1: MF: Panasonic Electronic; Manufacture_Name: PANASONIC; Manufacture_Part_Number: ERA-2AEB103X; Part Description: RES 10K OHM 0.1% 0402; Part Number: 03-2000086
R42 = SMALL_R1: MF: Vishay; Manufacture_Name: Vishay; Manufacture_Part_Number: TNPW04024K32BEED; Part Description: RES 4.32K OHM 0.1% 0402; Part Number: 03-2000087
R97 R125 R127 = SMALL_R1: MF: Panasonic Electronic; Manufacture_Name: PANASONIC; Manufacture_Part_Number: ERA-2VEB1800X; Part Description: RES 180 OHM 0.1% 0402; Part Number: 03-2000088
R105 R252 = SMALL_R1: MF: KOA; Manufacture_Name: KOA; Manufacture_Part_Number: RN73H1ETTP1001B25; Part Description: RES 1K OHM 0.1% 0402; Part Number: 03-2000089
R112 R159 R160 R267 R310 R317 = SMALL_R1: Manufacture_Name: WALSIN; Manufacture_Part_Number: WR04X1002FTL; Part Description: RES 10K OHM 1% 1/16W 0402; Part Number: 03-2000022; Price: 0.0002; Datasheet: https://www.digikey.com/en/products/detail/walsin-technology-corporation/WR04X1002FTL/13241339?s=N4IgTCBcDaIOoCUAMAWAGgRiUsAxAKgDIgC6AvkA
R124 R126 = SMALL_R1: MF: Panasonic Electronic; Manufacture_Name: PANASONIC; Manufacture_Part_Number: ERA-2AEB8251X; Part Description: RES 8.25K OHM 0.1% 0402; Part Number: 03-2000090
R247 R248 R265 R308 = SMALL_R1: Manufacture_Name: WALSIN; Manufacture_Part_Number: WR06X000 PTL; Part Number: 03-4000004; Price: 0.0004
R249 = SMALL_R1: MF: Panasonic Electronic; Manufacture_Name: WALSIN; Manufacture_Part_Number: WR04X4701FTL; Part Number: 03-2000038; Price: 0.0002
R250 = SMALL_R1: MF: KOA; Manufacture_Name: WALSIN; Manufacture_Part_Number: WR04X2700FTL; Part Description: RES 270 OHM 1%  1/16W 0402; Part Number: 03-2000091; Price: 0.0002
R321 = SMALL_R1: MF: Panasonic Electronic; Manufacture_Name: YAGEO; Manufacture_Part_Number: RT0402BRE0718KL; Part Description: RES 18K OHM 0.1% 0402; Part Number: 03-2000083
R322 = SMALL_R1: MF: KOA; Manufacture_Name: WALSIN; Manufacture_Part_Number: WR04X2701FTL; Part Description: RES 2.7K OHM 1% 1/16W 0402; Part Number: 03-2000092; Price: 0.0002
U2 = AP2318AMP-ADJTRG1_0: MF: ON Semiconductor; Manufacture_Name: ONSEMI; Part Description: IC REG LIN POS ADJ 500MA 8SOIC; Part Number: 06-0000041
VR1 = VAR_REG_0: MF: RICHTEK; Manufacture_Name: RICHTEK; Part Number: 06-0000004; Price: 0.065
VR2 VR3 = VAR_REG_0: MF: Diodes Incorporated; Manufacture_Name: RICHTEK; Part Number: 06-0000004; Price: 0.065
C27 C31 C33 C37 C39 = SMALL_CAP: MF: Murata Electronics; Manufacture_Name: MURATA; Manufacture_Part_Number: GRM155R60J475ME47D; Part Number: 01-2000014; Price: 0.003; Datasheet: https://www.digikey.com/en/products/detail/murata-electronics/GRM155R60J475ME47D/3694656?s=N4IgTCBcDaIOICUCyBGArGhA2ADAKQBYB2NJAUWIBEQBdAXyA
C29 C35 = SMALL_CAP: MF: TDK Corporation; Manufacture_Name: TDK; Manufacture_Part_Number: C1608JB1C335K080AC; Part Description: CAP CER 3.3UF 16V JB 0603; Part Number: 01-3000004; Price: 0.0104
C46 C47 = SMALL_CAP: MF: WALSIN; Manufacture_Name: WALSIN; Manufacture_Part_Number: 0402N270J500CT; Part Number: 01-2000024; Price: 0.001
L10 L11 = INDUCTOR: MF: Murata Electronics; Manufacture_Name: MURATA; Manufacture_Part_Number: BLM15KD300SN1D; Part Number: 02-2000008; Price: 0.0034
R25 = SMALL_R1: MF: WALSIN; Manufacture_Name: YAGEO; Manufacture_Part_Number: RC0402FR-0712KL; Part Description: RES 12K OHM 1% 0402; Part Number: 03-2000078; Price: 0.0002; Datasheet: https://www.digikey.com/en/products/detail/yageo/RC0402FR-0712KL/726532
R26 = SMALL_R1: MF: WALSIN; Manufacture_Name: YAGEO; Manufacture_Part_Number: RC0402JR-07470RL; Part Number: 03-2000012; Price: 0.0002; Datasheet: https://www.digikey.com/en/products/detail/yageo/RC0402JR-07470RL/726482?s=N4IgTCBcDaIEoGEAMAWJYBScC0SDsKeScAMiALoC%2BQA
R39 R40 = SMALL_R1: MF: TA-I; Manufacture_Name: WALSIN; Manufacture_Part_Number: WR04X10R0FTL; Part Number: 03-2000002; Price: 0.0002
R55 R56 R92-R94 R176 R197-R202 R302 R306 R323 R324 = SMALL_R1: MF: WALSIN; Manufacture_Name: WALSIN; Manufacture_Part_Number: WR04X4701FTL; Part Number: 03-2000038; Price: 0.0002
R188 R254 R259 R303 R325 R326 = SMALL_R1: MF: WALSIN; Part Number: 03-2000042
U7 = FT4232HQ-REEL_3: MF: FDTI; Manufacture_Name: FDTI; Part Number: 05-0000008; Price: 5.5
U8 = MiniUSB_0: MF: Contact Technology Corp.; Manufacture_Name: Contact Technology Corp.; Part Number: 07-0000007; Price: 0.5
U10 = 93LC56BT-I_OT: MF: Microchip Technology; Manufacture_Name: MICROCHIP; Manufacture_Part_Number: 93LC56BT-I/OT; Part Number: 05-0000010; Price: 0.21
Y1 = XTAL-OSC-4P_0: MF: Kyocera; Manufacture_Name: Kyocera; Manufacture_Part_Number: CX3225SB12000H0FLJCC; Part Description: CRYSTAL 12.0000MHZ 12PF SMD; Part Number: 06-0000060; Price: 0.35
C116-C121 C125 C126 = SMALL_CAP: Manufacture_Name: TAIYO-YUDEN; Manufacture_Part_Number: TMK105BJ104KV-F; Part Number: 01-2000003; Price: 0.0013; Datasheet: https://www.digikey.com/en/products/detail/taiyo-yuden/TMK105BJ104KV-F/1004044
J13 = CON-4X2-F: Manufacture_Name: Amphenol ICC (FCI); Manufacture_Part_Number: 68602-208HLF; Part Number: 08-0000024
JP58-JP64 = JUMPER-2: MF: Amphenol ICC (FCI); Manufacture_Name: AMPHENOL ICC (FCI); Manufacture_Part_Number: 68000-102HLF; Part Number: 08-0000002; Price: 0.0066; Datasheet: https://www.digikey.com/products/en?keywords=68000-102HLF
R283 R285 R287 R289-R291 R300 = SMALL_R1: Manufacture_Name: YAGEO; Manufacture_Part_Number: RC0402JR-071ML; Part Number: 03-2000030; Price: 0.0002; Datasheet: https://www.digikey.com/product-detail/en/yageo/RC0402JR-071ML/311-1.0MJRCT-ND/729356
U32-U37 U41 U42 = NX3DV2567: Manufacture_Name: NXP; Manufacture_Part_Number: NX3DV2567GU115; Part Description: NXP - NX3DV2567GU,115 - Analogue Switch, 4 Channels, 4PDT, 0.85 ohm, 1.4V to 4.3V, XQFN, 16 Pins; Part Number: 05-0000007; Datasheet: https://www.mouser.com/ProductDetail/NXP-Semiconductors/NX3DV2567GU115?qs=67TfscD5Pafw%252BgjlE0rl%2Fg%3D%3D
C108-C115 = SMALL_CAP: Manufacture_Name: MURATA; Manufacture_Part_Number: GRM155R61E104KA87; Part Number: 01-2000043; Price: 0.0013; Datasheet: https://www.murata.com/products/productdetail.aspx?partno=GRM155R61E104KA87%23
Q15-Q18 Q20 Q21 = MPF990_0: Manufacture_Name: DIODES; Part Description: MOSFET N-CH 50V 200MA SOT23-3; Part Number: 06-0000088; Datasheet: https://www.digikey.tw/en/products/detail/diodes-incorporated/BSS138-7-F/717723
R43 R47 R194-R196 R211-R216 R255-R258 R269-R272 R274-R276 R278 R279 R298 R304 R307 = SMALL_R1: MF: YAGEO; Manufacture_Name: YAGEO; Manufacture_Part_Number: RC0402JR-0733RL; Part Number: 03-2000003; Price: 0.0002; Datasheet: https://www.digikey.com/en/products/detail/yageo/RC0402JR-0733RL/726467?s=N4IgTCBcDaIDoBcAEAlAwgBgCwbAKRQFoMB2AZjJQBkQBdAXyA
R245 = SMALL_R1: Manufacture_Name: YAGEO; Manufacture_Part_Number: RC0402JR-07100KL; Part Number: 03-2000020; Price: 0.0002; Datasheet: https://www.digikey.com/en/products/detail/yageo/RC0402JR-07100KL/726416
R246 R305 R327-R329 = SMALL_R1: Part Number: 03-2000042
R253 R260 = SMALL_R1: MF: YAGEO; Manufacture_Name: WALSIN; Manufacture_Part_Number: WR04X1000FTL; Part Description: RES 100 OHM 1% 1/16W 0402; Part Number: 03-2000044; Price: 0.0002
R261 R262 = SMALL_R1: MF: YAGEO; Manufacture_Name: PANASONIC; Manufacture_Part_Number: ERJ-2GE0R00X; Part Number: 03-2000018; Price: 0.0002; Datasheet: https://www.digikey.com/en/products/detail/panasonic-electronic-components/erj-2ge0r00x/146727
R263 R264 R297 R330 R331 = SMALL_R1: MF: YAGEO; Part Number: 03-2000042
R332 = SMALL_R1: MF: WALSIN; Manufacture_Name: WALSIN; Manufacture_Part_Number: WR04X1000FTL; Part Description: RES 100 OHM 1% 1/16W 0402; Part Number: 03-2000044; Price: 0.0002
U6 = NTB0104: MF: Texas Instruments; Manufacture_Name: TEXAS INSTRUMENTS; Manufacture_Part_Number: LSF0204RUTR; Part Number: 05-0000011
U26 U27 U29 = NTB0104_0: Manufacture_Name: TI; Part Description: IC XLTR VL UNIDIR 12-UQFN HIGH ACTIVE; Part Number: 05-0000042; Datasheet: https://www.digikey.tw/zh/products/detail/texas-instruments/TXU0104RUTR/14835767
U28 = 54AS00_1: Manufacture_Name: NEXPERIA; Part Description: AND Gate IC 1 Channel SC-74A, 1.65~6.5V; Part Number: 05-0000034; Datasheet: https://www.digikey.com/en/products/detail/nexperia-usa-inc/74lvc1g08gv-125/1231422
CN1 = FFC_14PIN_0_2.5MM_D: Manufacture_Name: Yeonho Elect; Part Description: FFC/Female/14PIN/0.5MM/D; Part Number: 07-0000028; Price: 0.107; Vendor: MOLEX; Datasheet: https://www.alldatasheet.com/datasheet-pdf/pdf/147754/YEONHO/05002HR-14C.html
J1 = HEADER_10X2: MF: Sullins Connector Solutions; Manufacture_Name: SULLINS; Manufacture_Part_Number: SFH11-PBPC-D10-RA-BK; Part Description: CONN HDR(FEMALE) 20POS 2.54MM R/A; Part Number: 08-0000008
J2-J6 J11 J18 = HEADER_3: Manufacture_Name: AMPHENOL ICC (FCI); Manufacture_Part_Number: 68000-103HLF; Part Number: 08-0000003; Datasheet: https://www.digikey.tw/en/products/detail/amphenol-cs-fci/68000-103HLF/2023309?s=N4IgTCBcDaIGwA4AMKC0BGJBmAEgGQDEQBdAXyA
R268 R311 = SMALL_R1: Manufacture_Name: YAGEO; Manufacture_Part_Number: RC0402JR-07470RL; Part Number: 03-2000012; Price: 0.0002; Datasheet: https://www.digikey.com/en/products/detail/yageo/RC0402JR-07470RL/726482?s=N4IgTCBcDaIEoGEAMAWJYBScC0SDsKeScAMiALoC%2BQA
R273 = SMALL_R1: Part Number: 03-4000017
R277 R280-R282 R284 R286 R288 = SMALL_R1: Manufacture_Name: WALSIN; Manufacture_Part_Number: WR04X1001FTL; Part Description: RES 1K OHM 1% 0402; Part Number: 03-2000028; Price: 0.0002; Datasheet: https://www.digikey.com/en/products/detail/walsin-technology-corporation/WR04X1001FTL/13240628?s=N4IgTCBcDaIOoCUAMAWAGgRiUjAxAKgDIgC6AvkA
U24 U25 = PGB1010603: MF: Littelfuse Inc.; Manufacture_Name: LITTELFUSE; Part Number: 06-0000003; Price: 0.0095
U30 U31 U43 U44 = TLP241AD4: Manufacture_Name: Toshiba Semiconductor; Manufacture_Part_Number: TLP241A(D4,F; Part Description: Solid State SPST-NO (1 Form A) 4-DIP (0.300", 7.62mm); Part Number: 05-0000039; Price: 1.73; Datasheet: https://www.digikey.tw/en/products/detail/toshiba-semiconductor-and-storage/TLP241A-D4-F/7809667
J7 J8 = HEADER-6X2_0: Manufacture_Name: AMPHENOL ICC (FCI); Manufacture_Part_Number: PH2-12-UA; Part Description: CONN HEADER VERT 12POS 2.54MM; Part Number: 08-0000035; Datasheet: https://www.digikey.com/product-detail/en/adam-tech/PH2-12-UA/2057-PH2-12-UA-ND/9830397
FD1-FD4 = TEST_POINT: Part Number: 09-0000007
J16 = HEADER_7: Manufacture_Name: AMPHENOL ICC (FCI); Manufacture_Part_Number: 68000-107HLF; Part Description: CONN HEADER VERT 7POS 2.54MM; Part Number: 08-0000046; Datasheet: https://www.digikey.com/en/products/detail/amphenol-cs-fci/68000-107HLF/4273218?s=N4IgTCBcDaIGwA4AMKC0BGJB2AEgGQDEQBdAXyA
MT1-MT4 = TEST_POINT: Part Number: 09-0000006
R108 = R_0: MF: YAGEO; Part Number: 03-2000042
R109 = R_0: MF: WALSIN; Manufacture_Name: YAGEO; Manufacture_Part_Number: RC0402JR-07100KL; Part Number: 03-2000020; Price: 0.0002; Datasheet: https://www.digikey.com/en/products/detail/yageo/RC0402JR-07100KL/726416
R334 = R_0: MF: WALSIN; Manufacture_Name: WALSIN; Manufacture_Part_Number: WR04X10R0FTL; Part Number: 03-2000002; Price: 0.0002
S1 S2 = SW-TACT-4P-5: Manufacture_Name: C&K; Manufacture_Part_Number: PTS645SK50SMTR92 LFS; Part Number: 07-0000016
TP13-TP17 = TP_0
R314 R316 = SMALL_R1: Manufacture_Name: WALSIN; Manufacture_Part_Number: WR04X10R0FTL; Part Number: 03-2000002; Price: 0.0002

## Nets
4.36V: C8.2 C9.2 C104.1 L1.1 L4.1 L6.1 R3.2 R11.1 TP15.1(TP) U2.5(VOUT) U2.6(VOUT)
5V: C10.2 C11.2 L12.2 R2.2 R10.2 TP14.1(TP) U2.3(VIN) U2.4(VIN)
GND_SIGNAL: C5.1 C6.1 C7.1 C8.1 C9.1 C10.1 C11.1 C16.1 C17.2 C19.1 C20.2 C25.1 C26.1 C27.1 C28.2 C29.1 C30.2 C31.1 C32.2 C33.1 C34.2 C35.1 C36.2 C37.1 C38.2 C39.1 C40.2 C46.2 C47.2 C52.2 C53.2 C101.1 C106.1 C108.1 C109.1 C110.1 C111.1 C112.1 C113.1 C114.2 C115.2 C116.2 C117.2 C118.2 C119.2 C120.2 C121.2 C125.2 C126.2 CN1.8 CN1.15 CN1.16 DS2.1(CATHODE) DS3.1(CATHODE) DS4.1(CATHODE) DS5.1(CATHODE) DS6.1(CATHODE) J1.19 J11.1 J11.2 J11.3 J14.3 J14.4 J15.2 J15.4 J15.6 JP60.2 MT1.1 MT2.1 MT3.1 MT4.1 Q15.2(SOURCE) Q16.2(SOURCE) Q17.2(SOURCE) Q18.2(SOURCE) Q20.2(SOURCE) Q21.2(SOURCE) R8.2 R25.2 R55.1 R56.1 R92.1 R93.1 R94.1 R97.2 R108.1 R109.1 R176.1 R188.2 R197.1 R198.1 R199.1 R200.1 R201.1 R202.1 R245.2 R254.2 R259.2 R283.1 R285.1 R287.1 R289.1 R290.1 R291.1 R300.1 R302.1 R303.1 R314.2 R316.2 R317.2 R323.2 R324.2 S2.1 S2.2 TP13.1(TP) U2.1(GND) U6.6(GND) U7.1(GND) U7.5(GND) U7.10(AGND) U7.11(GND) U7.13(TEST) U7.15(GND) U7.25(GND) U7.35(GND) U7.47(GND) U7.51(GND) U7.65(EPAD) U8.4(GND) U8.5(GND) U8.6(GND) U10.2(VSS) U24.2(..) U25.2(..) U26.6(GND) U27.6(GND) U28.3(GND) U29.6(GND) U30.2(CATHODE) U31.2(CATHODE) U32.6(GND) U33.6(GND) U34.6(GND) U35.6(GND) U36.6(GND) U37.6(GND) U41.6(GND) U42.6(GND) U43.2(CATHODE) U44.2(CATHODE) VR1.2(GND) VR2.2(GND) VR3.2(GND) Y1.2(NC) Y1.4(NC)
VBAT_EN: J2.2 R277.2 R280.2 R281.2
VCC_1P8_FTDI: C29.2 C30.1 C35.2 C36.1 U7.12(VCORE) U7.37(VCORE) U7.49(VREGOUT) U7.64(VCORE)
VCC_3V3_BD: C31.2 C32.1 C37.2 C38.1 J2.1 L10.1 L11.1 R28.1 R29.1 R30.1 R31.1 R247.2 R265.1 R306.2 R308.1 U7.20(VCCIO) U7.31(VCCIO) U7.42(VCCIO) U7.50(VREGIN) U7.56(VCCIO) U10.6(VCC)
VCC_3V3_BD_ALL: C4.2 C5.2 R4.2 R9.1 R247.1 R248.1 VR1.5(VOUT)
VCC_3V3_LS: C26.2 C108.2 C111.2 C112.2 C125.1 C126.1 JP59.1 JP64.2 R248.2 R260.1 U6.11(VCCB) U26.1(VCCA) U27.1(VCCA) U28.5(VCC) U29.11(VCCB) U41.14(VCC) U42.14(VCC)
VCC_5V_USB: C39.2 C40.1 L12.1 U8.1(VCC)
VCC_BAT: C105.2 C106.2 R5.2 R99.1 TP16.1(TP) U30.4(DRAIN_2) VR2.5(VOUT)
VCC_BAT_DUT: C53.1 C114.1 CN1.14 J1.2 JP58.2 JP61.2 R273.2 U24.1(.)
VCC_BAT_O: JP58.1 R273.1 R327.1 U30.3(DRAIN)
VCCIO: C25.2 C100.2 C101.2 C109.2 C110.2 C113.2 C116.1 C117.1 C118.1 C119.1 C120.1 C121.1 J3.1 J4.1 J5.1 J6.1 R6.2 R96.1 R119.2 R253.1 R332.1 TP17.1(TP) U6.1(VCCA) U26.11(VCCB) U27.11(VCCB) U29.1(VCCA) U31.4(DRAIN_2) U32.14(VCC) U33.14(VCC) U34.14(VCC) U35.14(VCC) U36.14(VCC) U37.14(VCC) VR3.5(VOUT)
VCCIO_DUT: C52.1 C115.1 CN1.13 J1.1 JP61.1 R328.1 S1.1 S1.2 U25.1(.) U31.3(DRAIN)
BAT_1V5: J14.6 R322.2
BAT_2V5: J14.5 R125.2
BAT_3V: J14.2 R105.2
BAT_3V7: J14.1 R250.2
BBOOT1: R255.1 U28.4(Y)
BBOOT&U1_RX: U26.7(B4) U34.8(3Z)
BBOOT&U1_RX_DUT: J16.2 R214.2 R270.2 U34.7(3Y1)
CTRL_EN1: J3.3 R246.1 R256.2 R282.1
CTRL_EN2: J5.3 R257.2 R286.1 R304.1
DBUS1_CTRL_EN3: R258.2 R305.2
DBUS2_GPIO_SW: J6.3 R288.1 R298.2 R329.2
DBUS_CTRL: JP59.2 R300.2 U41.2(S) U42.2(S)
FTDI_ABUS3_VBAT_EN: R94.2 U7.19(ADBUS3) U41.13(4Y0)
FTDI_ABUS4_CTRL_EN1: R92.2 U7.21(ADBUS4) U41.9(3Y0)
FTDI_ABUS5_CTRL_EN2: R93.2 U7.22(ADBUS5) U41.5(2Y0)
FTDI_ABUS6_BBOOT: R55.2 U7.23(ADBUS6) U42.13(4Y0)
FTDI_ABUS7_PWD_RESET: R56.2 U7.24(ADBUS7) U42.5(2Y0)
FTDI_BBOOT: JP64.1 R297.1 U28.2(B) U42.12(4Z)
FTDI_BBUS2_RTS: R324.1 R326.1 U7.28(BDBUS2)
FTDI_BBUS4_DTR: R323.1 R325.1 U7.30(BDBUS4)
FTDI_CTRL_EN1: JP62.2 U27.2(A1) U41.8(3Z)
FTDI_CTRL_EN2: JP63.1 U27.3(A2) U41.4(2Z)
FTDI_DBUS0_INT: J13.2 J18.3 JP60.1 R303.2 R306.1 R307.2 S2.3 S2.4 U7.48(DDBUS0)
FTDI_DBUS1_CTRL_EN3: J13.1 JP63.2 R302.2 U7.52(DDBUS1) U27.4(A3)
FTDI_DBUS2_GPIO_SW: J13.4 R176.2 U7.53(DDBUS2) U27.5(A4)
FTDI_DBUS3_VBAT_EN: J13.3 R202.2 U7.54(DDBUS3) U41.11(4Y1)
FTDI_DBUS4_CTRL_EN1: J13.6 R201.2 U7.55(DDBUS4) U41.7(3Y1)
FTDI_DBUS5_CTRL_EN2: J13.5 R200.2 U7.57(DDBUS5) U41.3(2Y1)
FTDI_DBUS6_BBOOT: J13.8 R199.2 U7.58(DDBUS6) U42.11(4Y1)
FTDI_DBUS7_PWD_RESET: J13.7 R198.2 U7.59(DDBUS7) U42.3(2Y1)
FTDI_PWD_RESET: U26.4(A3) U42.4(2Z)
FTDI_RESET: R28.2 U7.14(~{RESET#})
FTDI_SWDCLK: R261.2 R330.2 U7.16(ADBUS0)
FTDI_SWDIO: R26.2 R262.2 R331.2 U7.18(ADBUS2)
FTDI_UART0_CTS: U7.41(CDBUS3) U29.8(B3)
FTDI_UART0_RTS: R197.2 U7.40(CDBUS2) U26.3(A2)
FTDI_UART0_RX: U7.39(CDBUS1) U29.9(B2)
FTDI_UART0_TX: U7.38(CDBUS0) U26.2(A1)
FTDI_UART1_RX: U7.27(BDBUS1) U29.10(B1)
FTDI_UART1_TX: U7.26(BDBUS0) U28.1(A)
FTDI_VBAT_EN: J2.3 JP62.1 R281.1 U41.12(4Z)
GPIO1-1(P): J7.1 U35.16(1Z)
GPIO1-2(P): J7.2 U35.15(1Y1)
GPIO2-1: J7.3 U35.4(2Z)
GPIO2-2: J7.4 U35.3(2Y1)
GPIO3-1: J7.5 U35.8(3Z)
GPIO3-2: J7.6 U35.7(3Y1)
GPIO4-1: J7.7 U35.12(4Z)
GPIO4-2: J7.8 U35.11(4Y1)
GPIO5-1(P): J7.9 U36.16(1Z)
GPIO5-2(P): J7.10 U36.15(1Y1)
GPIO6-1: J7.11 U36.4(2Z)
GPIO6-2: J7.12 U36.3(2Y1)
GPIO7-1: J8.1 U36.8(3Z)
GPIO7-2: J8.2 U36.7(3Y1)
GPIO8-1: J8.3 U36.12(4Z)
GPIO8-2: J8.4 U36.11(4Y1)
GPIO9-1(P): J8.5 U37.16(1Z)
GPIO9-2(P): J8.6 U37.15(1Y1)
GPIO10-1: J8.7 U37.4(2Z)
GPIO10-2: J8.8 U37.3(2Y1)
GPIO11-1: J8.9 U37.8(3Z)
GPIO11-2: J8.10 U37.7(3Y1)
GPIO12-1: J8.11 U37.12(4Z)
GPIO12-2: J8.12 U37.11(4Y1)
GPIO_EN: J6.2 R288.2 R289.2 R290.2 R291.2 U35.2(S) U36.2(S) U37.2(S)
PWD_RESET: U26.8(B3) U34.16(1Z)
PWD_RESET_DUT: J16.6 R109.2 R216.2 R269.2 R333.1 R334.2
SWDCLK: R43.1 R263.1 U32.8(3Z)
SWDCLK_DUT: J16.1 R194.1 R272.2 U32.7(3Y1)
SWDIO: R47.1 R264.1 U32.4(2Z)
SWDIO_DUT: J16.3 R195.1 R271.2 U32.3(2Y1)
UART0_CTS: U26.9(B2) U34.12(4Z)
UART0_CTS_DUT: J18.2 R212.1 R278.2 U34.11(4Y1)
UART0_RTS: U29.4(A3) U33.12(4Z)
UART0_RTS_DUT: J18.1 R213.1 R276.2 U33.11(4Y1)
UART0_RX: U26.10(B1) U33.8(3Z)
UART0_RX_DUT: J16.5 R196.1 R274.2 U33.7(3Y1)
UART0_TX: U29.3(A2) U33.4(2Z)
UART0_TX_DUT: J16.7 R211.1 R275.2 U33.3(2Y1)
UART1_TX: U29.2(A1) U34.4(2Z)
UART1_TX_DUT: J16.4 R215.2 R279.2 U34.3(2Y1)
VIO_1V8: J15.5 R42.2
VIO_2V5: J15.3 R127.2
VIO_3V: J15.1 R252.2
N16857263: C6.2 C7.2 L1.2 R160.1 VR1.1(VIN)
N16857297: C4.1 R9.2 R12.1 VR1.4(FB)
N16857401: C16.2 C17.1 L4.2 R159.1 VR2.1(VIN)
N16857596: C19.2 C20.1 L6.2 R112.1 VR3.1(VIN)
N16860548: C27.2 C28.1 L10.2 U7.9(VPLL)
N16860666: C33.2 C34.1 L11.2 U7.4(VPHY)
N16860980: R26.1 U7.17(ADBUS1)
N16861063: R25.1 U7.6(REF)
N16861161: R32.1 U10.1(DO)
N16861167: R29.2 R32.2 U7.61(EEDATA) U10.3(DI)
N16861169: R30.2 U7.62(EECLK) U10.4(CLK)
N16861171: R31.2 U7.63(EECS) U10.5(CS)
N16861233: C46.1 U7.2(OSCI) Y1.1(HOT)
N16861281: C47.1 U7.3(OSCO) Y1.3(HOT)
N16880318: DS2.2(ANODE) R2.1
N16880320: DS3.2(ANODE) R3.1
N16880322: DS4.2(ANODE) R4.1
N16880324: DS5.2(ANODE) R5.1
N16880326: DS6.2(ANODE) R6.1
N16961290: R10.1 U2.2(SD)
N16963260: C104.2 R8.1 R11.2 U2.7(FB)
N17120306: R40.1 U7.7(DM)
N17120315: R40.2 U8.2(D-)
N17120320: R39.2 U8.3(D+)
N17120323: R39.1 U7.8(DP)
N17179216: C100.1 R14.1 R96.2 R126.1 R251.1 VR3.4(FB)
N17184341: R12.2 R97.1
N17190503: R14.2 R42.1
N17192597: C105.1 R99.2 R123.1 R124.1 R249.1 R321.1 VR2.4(FB)
N17192665: R124.2 R125.1
N17193181: R105.1 R123.2
N17207291: R112.2 VR3.3(EN)
N17213032: R126.2 R127.1
N17257970: R249.2 R250.1
N17263114: R159.2 VR2.3(EN)
N17263425: R160.2 VR1.3(EN)
N17280189: R265.2 R266.1 R267.1 R268.1
N17280209: DS7.2(ANODE) R266.2
N17280235: DS7.1(CATHODE) Q16.3(DRAIN)
N17280237: Q17.1(GATE) Q18.3(DRAIN) R267.2
N17280239: Q17.3(DRAIN) R268.2 U30.1 U31.1
N17280298: Q16.1(GATE) R277.1
N17280356: Q18.1(GATE) R280.1
N17280756: J3.2 R282.2 R283.2 U32.2(S)
N17282677: J4.2 R284.2 R285.2 U33.2(S)
N17282687: J4.3 R284.1 R304.2 R305.1
N17283026: J5.2 R286.2 R287.2 U34.2(S)
N17296581: R108.2 R334.1 S1.3 S1.4
N17296970: Q15.3(DRAIN) R119.1 U6.12(OE)
N17297037: R43.2 U6.2(A1)
N17297053: R47.2 U6.3(A2)
N17297662: R188.1 R253.2 U26.12(OE)
N17297783: R255.2 R297.2 U26.5(A4)
N17297842: R254.1 R332.2 U27.12(OE)
N17297901: R256.1 U27.10(B1)
N17297917: R257.1 U27.9(B2)
N17297933: R258.1 U27.8(B3)
N17297982: R259.1 R260.2 U29.12(OE)
N17299290: J1.3 R194.2
N17299293: J1.5 R195.2
N17299296: J1.7 R196.2
N17299299: J1.9 R211.2
N17299302: J1.11 R213.2
N17299305: J1.13 R212.2
N17299411: J1.6 R215.1
N17299412: J1.8 R216.1
N17299413: J1.4 R214.1
N17299708: CN1.11 R270.1
N17299721: CN1.1 R279.1
N17299734: CN1.12 R269.1
N17300020: CN1.4 R275.1
N17300023: CN1.5 R274.1
N17300026: CN1.7 R271.1
N17300029: CN1.9 R272.1
N17300238: CN1.3 R276.1
N17300241: CN1.2 R278.1
N17314136: R251.2 R252.1
N17322717: Q15.1(GATE) R245.1 R246.2
N17331014: R261.1 U6.10(B1)
N17331017: R262.1 U6.9(B2)
N17390713: R298.1 U27.7(B4)
N17408123: J1.20 R307.1
N17412320: R308.2 R310.1 R311.1
N17412358: Q20.1(GATE) Q21.3(DRAIN) R310.2
N17412360: Q20.3(DRAIN) R311.2 U43.1 U44.1
N17412410: R314.1 U43.3(DRAIN)
N17412965: R316.1 U44.3(DRAIN)
N17413233: Q21.1(GATE) R317.1 R329.1
N17413284: R327.2 U43.4(DRAIN_2)
N17413295: R328.2 U44.4(DRAIN_2)
N17413689: R321.2 R322.1
N17436762: R263.2 R330.1
N17436765: R264.2 R331.1
N17465413: R333.2 U34.15(1Y1)

Not connected (* = marked no-connect by the designer): CN1 6* 10*; FD1 1*; FD2 1*; FD3 1*; FD4 1*; J1 10* 12* 14* 15* 16* 17* 18*; R325 2*; R326 2*; U2 8(NC)*; U6 4(A3)* 5(A4)* 7(B4)* 8(B3)*; U7 29(BDBUS3)* 32(BDBUS5)* 33(BDBUS6)* 34(BDBUS7)* 36(~{SUSPEND#})* 43(CDBUS4)* 44(CDBUS5)* 45(CDBUS6)* 46(CDBUS7)* 60(~{PWREN#})*; U29 5(A4)* 7(B4)*; U32 1(1Y0)* 5(2Y0)* 9(3Y0)* 10(N_C_)* 11(4Y1)* 12(4Z)* 13(4Y0)* 15(1Y1)* 16(1Z)*; U33 1(1Y0)* 5(2Y0)* 9(3Y0)* 10(N_C_)* 13(4Y0)* 15(1Y1)* 16(1Z)*; U34 1(1Y0)* 5(2Y0)* 9(3Y0)* 10(N_C_)* 13(4Y0)*; U35 1(1Y0)* 5(2Y0)* 9(3Y0)* 10(N_C_)* 13(4Y0)*; U36 1(1Y0)* 5(2Y0)* 9(3Y0)* 10(N_C_)* 13(4Y0)*; U37 1(1Y0)* 5(2Y0)* 9(3Y0)* 10(N_C_)* 13(4Y0)*; U41 1(1Y0)* 10(N_C_)* 15(1Y1)* 16(1Z)*; U42 1(1Y0)* 7(3Y1)* 8(3Z)* 9(3Y0)* 10(N_C_)* 15(1Y1)* 16(1Z)*

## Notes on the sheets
sheet 1
- MP DOWNLOAD BOARD(DL)
- Release Date
- Revision
- Design Eng.
- Design Note
- 8/11/2020
- Rev. 1
- JOE
- Initial release
- 8/20/2020
- Rev. 2
- JOE
- 1. Reduce Jump numbers
  2. Add 1.8V VDDIO Jump
- 9/28/2020
- Rev. 3
- JOE
- 1. Replace the unidirection level shift U12
     for BBOOT and PWD
  2. Change VBAT and VCCIO 3.3V option to 3V.
     R17 and R20 change to 0ohm
- 10/26/2021
- Rev. 4
- JOE
- 1. Switching regulator U4 change from PWM mode to hysteresis mode, R18 connect
     to ground.
  2. Add a GPIO1 control option from U1-pin24 (ADBUS4) to J1 2x10 connector pin17
  3. Add S1 button to resut DUT
- 03/07/2022
- Rev. 5
- JOE
- 1. Add power control circuits for BAT/VCCIO/LS.
- 2. R43, R47, R51, R52, R53, R54, R57, R62, R122 change from 0 ohm to 62 ohm.
- 05/02/2022
- Rev. 6
- JOE
- 1. R43, R47, R51, R52, R53, R54, R57, R62, R122 change to 62 ohm.
- 2. Add FB1, FB2, FB3, FB4, FB5, FB6, FB7, FB8, FB9
- 02/24/2026
- Rev. 7
- JOE
- 1. Add photorelays and analog switches to enable connect/disconnect control of DUT VBAT,
     VCCIO, and control interfaces.
- 2. DUT VBAT voltage support: add 1.5V and 3.7V.
- 3. Add GPIO test functionality.
- 4. Add an 14 pin FPC connector to support atmosic reference design board.
- 5. Support GPIO interrupt-based trigger to start MPTool automated testing.
- 6. Y1-12MH crystal: Connect pins 2 and 4 from Not Connected (NC) to Ground.
- 04/07/2026
- Rev. 7a
- JOE
- 1. Replace the unidirectiuon level shifter from NL3V4T244MU2AG-Q to TXU0104DTR.
- 2. Connect a 1 kohm resistor R333 in series between pin 15 of U34 and PWD_RESET_DUT.
- 3. Change the connection between SWDCLK_DUT and R272 from pin 10 to pin 9 of the CN1
     FPC connector.
- Atmosic Technologies, Inc
- ATMOSIC TECHNOLOGIES INC
- Atmosic Technologies Proprietary and Confidential
sheet 2
- BLOCK DIAGRAM
- 3V3
- VCCIO
- Uni-direction
  Level Shifter
- CTRL_EN1
- 2x10 or FPC
  Connector
- CTRL_EN2
- FT4232
- (CTRL_EN3)
- AND
  Gate
- CTRL_EN2
- 3V3
- VCCIO
- VCCIO
- CTRL_EN3(Optional)
- BBOOT
- Uni-direction
  Level Shifter
- FDTI_UART1_TX
- USB
- D+/D-
- PWD/BBOOT
  UART0/UART1
- Analog SW
- DUT_PWD
- DUT_BBOOT/UART1_RX
- 5V
- PWD
- DUT_UART1
- PWD/BBOOT
  UART0/UART1
- LDO
- FDTI_UART0
  FDTI_UART1_RX
- Uni-direction
  Level Shifter
- DUT_UART0_TX
- NCP3334
- DUT_UART0_RX
- (Max. Vin 12V)
- UART0/UART1
- DUT_UART0_RTS(Option)
- DUT_UART0_CTS(Option)
- 3V3
- VCCIO
- VCCIO
- CTRL_EN1
- LDO-ADJ
- Bi-direction
  Level Shifter
- Analog SW
- DUT_SWD_IO
- 4.36V
- 3V3
- SWD
- RT9053AGB
- FT4232_VIO
- SWD
- DUT_SWD_CLK
- SWD
- (FT4232_VIO)
- GPIO_SW/
  DISCHARGE
  (option)
- 3V3
- VCCIO
- Uni-direction
  Level Shifter
- DBUS2_GPIO_SW
- BAT_EN
- VCCIO_EN
- AUTO_TEST_INT
- LDO-ADJ(VBAT)
- 4.36V
- RT9053AGB
- DUT_VBAT
- 3.7V/3.0V/2.5V/1.5V
- Relay
- Relay
  Discharge
  (Optional)
- LDO-ADJ(VCCIO)
- 4.36V
- RT9053AGB
- DUT_VCCIO
- 3V/2.5V/1.8V
- Relay
- 3V3
- AUTO_TEST INT
  (Low Active)
- Relay
  Discharge
  (Optional)
- ATMOSIC TECHNOLOGIES INC
- Analog SW
  Total 24Pins
  max. 12 pairs
- Two 2x6
  Connectors
- GPIOs Test
sheet 3
- POWER
- FT4232H_3V3
- FDTI GPIO
- PPTC
- LS 3.3V
- VIN Range (2.6V~12V,500mA ,Vdrouput=0.34V)
  VOUT = 1.25 x (1+(R11/R8))
  R11=24.9Kohm, R8=10Kohm
  VOUT=4.36V
- UDT_BAT
- DUT_BAT
- PPTC
- DUT_VDDIO
- DUT_VCCIO
- PPTC
- ATMOSIC TECHNOLOGIES INC
- ATMOSIC TECHNOLOGIES INC
sheet 4
- FT4232HQ
- TYPE B
  USB
- EEPROM
- 12MHz XTAL
- ATMOSIC TECHNOLOGIES INC
sheet 5
- Assert Pin1/2
  FT4232 DBUS control
- INPUT S
- CHANNEL ON
- ATMOSIC TECHNOLOGIES INC
- L
- nY0
- H
- nY1
sheet 6
- LEVEL_SHIFTER
- 74LVC1G08GV,125(AND)
- Uni-direction Level Shifter
- PIN1
  (FTDI_BBOOT)
- PIN2
  (FTDI_UART1_TX)
- PIN4
  (OUT)
- Uni-direction Level Shifter
- SUPPORT MODE
- H
- H
- H
- BBOOT and ROM_UART
- L
- H
- L
- NORMAL
- Note: Add a jumper to JP64 to manually pull high FTDI_BBOOT signal and
  then enable the UART1 bootloader firmware download function.
- Bi-direction Level Shifter
- Uni-direction Level Shifter
- ATMOSIC TECHNOLOGIES INC
sheet 7
- TLP241A
- POWER CONTROL
  VBAT/ VCCIO
- INTERFACE
- PIN1
- PIN3/PIN4
- 2x10-20PIN Connector
- 14PIN FPC Connector
- IF(VH)>5mA
- I(max)=1.3A,
  Ron(max)=0.15 ohm
- Power Control
  (LED Indicate)
- Assert Pin1/2 to enable
  (High Active)
- CURRENT
  MEASUREMENT
- NX3DV2567
- SIGNAL CONNECT/DISCONNECT SWITCH
  DUT SWD/UART0/UART1
- IN_S
- CHANNEL ON
- L
- nY0
- CTRL
- EN1
- EN2
- EN3(Option)
- SWD
- H(Active)
- X
- X
- H
- nY1
- UART0
- X
- H(Active)
  R304=33,
  R305=NC
  (Default)
- H(Active)
  R304=NC,
  R305=33
  (No FC)
- VCC=1.8V
  RON/I(mA)
- UART1
  (ROM BBOOT)
  (BBOOT/PWD)
- PORT
- X
- H(Active)
- X
- 1(P)
- 0.75ohm/100mA
- NOTE: UART0 can eaither control by  EN2
  (default) or EN3(no flow control) by BOM option.
- 2/3/4
- 10ohm/20mA
- Assert Pin1/2 to connect
  (High Active)
- Assert Pin1/2 to connect
  (High Active)
- Assert Pin1/2 to connect
  (High Active)
- ATMOSIC TECHNOLOGIES INC
sheet 8
- GPIO TEST
- Install PIN1/2 to
  conntec GPIO
- (High Active)
- Assert Pin1/2 to connect GPIOS
- INPUT S
- CHANNEL ON
- L
- nY0
- H
- nY1
- VCC=1.8V
  RON/I(mA)
- PORT
- ATMOSIC TECHNOLOGIES INC
- 1(P)
- 0.75ohm/100mA
- 2/3/4
- 10ohm/20mA
sheet 9
- TLP241A
- PIN1
- PIN3/PIN4
- I(max)=1.3A,
  Ron(max)=0.15 ohm
- IF(VH)>5mA
- ATMOSIC TECHNOLOGIES INC
sheet 10
- RESET
- POWER
- 5V
- 4.36V
- GND
- PTS645 SMD
- DUT
  VBAT
- DUT
  VCCIO
- TEST POINT-DUT
- AUTO TEST
- BOARD FIDUCIALS
- TEST POINT- CONTROL
- MOUNTING HOLES
- GND
- ATMOSIC TECHNOLOGIES INC
